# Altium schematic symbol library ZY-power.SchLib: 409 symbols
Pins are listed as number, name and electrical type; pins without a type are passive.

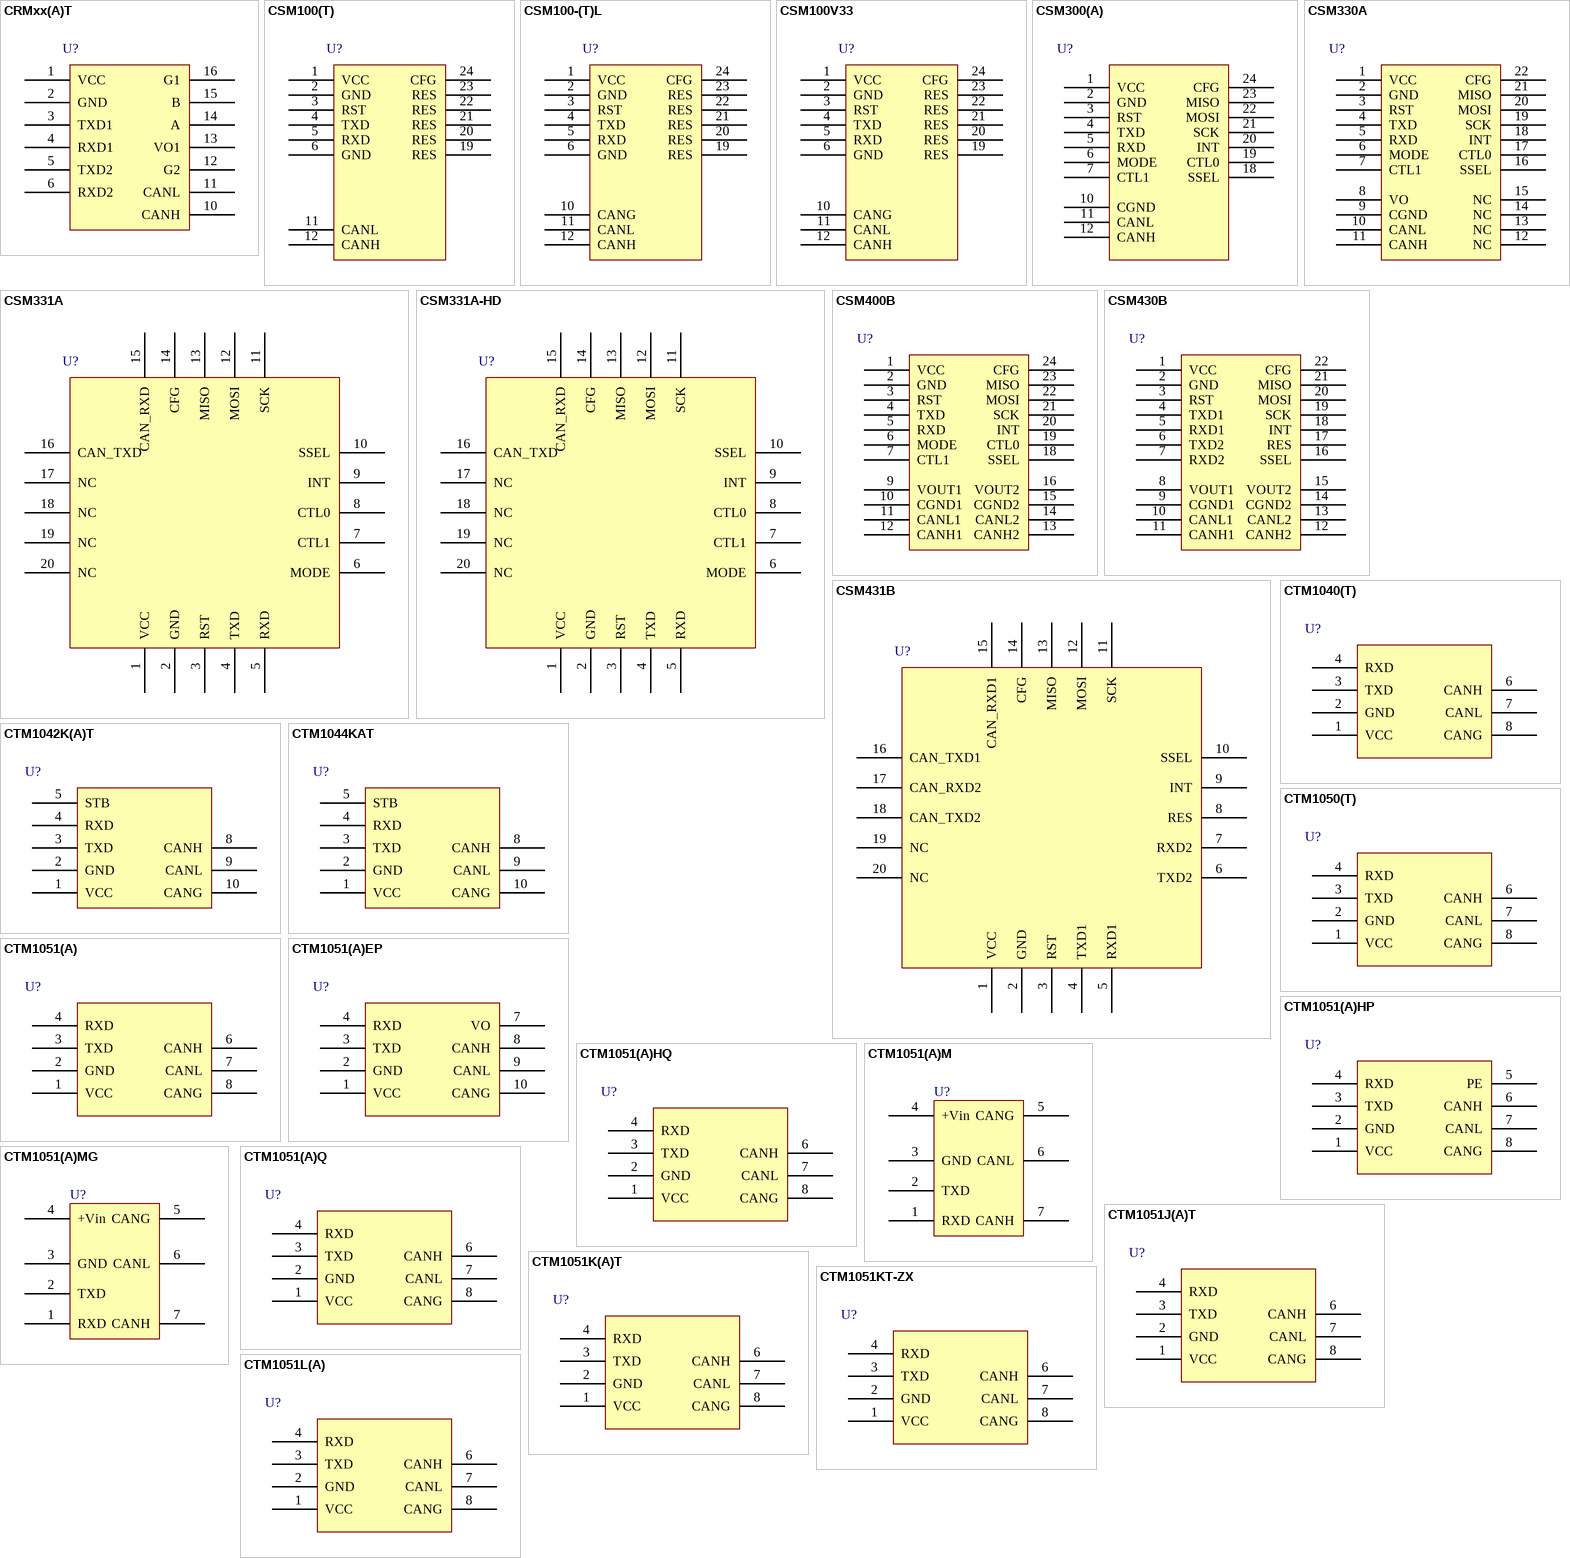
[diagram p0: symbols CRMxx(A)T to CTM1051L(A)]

## CRMxx(A)T
designator U?
footprint CRMxx(A)T
pins: 1 VCC, 2 GND, 3 TXD1, 4 RXD1, 5 TXD2, 6 RXD2, 10 CANH, 11 CANL, 12 G2, 13 VO1, 14 A, 15 B, 16 G1

## CSM100(T)
designator U?
footprint CSM100(T) (嵌入式CAN-bus接口芯片)
pins: 1 VCC, 2 GND, 3 RST, 4 TXD, 5 RXD, 6 GND, 11 CANL, 12 CANH, 19 RES, 20 RES, 21 RES, 22 RES, 23 RES, 24 CFG

## CSM100-(T)L
designator U?
footprint CSM100-(T)L
pins: 1 VCC, 2 GND, 3 RST, 4 TXD, 5 RXD, 6 GND, 10 CANG, 11 CANL, 12 CANH, 19 RES, 20 RES, 21 RES, 22 RES, 23 RES, 24 CFG

## CSM100V33
designator U?
footprint CSM100V33
pins: 1 VCC, 2 GND, 3 RST, 4 TXD, 5 RXD, 6 GND, 10 CANG, 11 CANL, 12 CANH, 19 RES, 20 RES, 21 RES, 22 RES, 23 RES, 24 CFG

## CSM300(A)
designator U?
footprint CSM300(A)
pins: 1 VCC, 2 GND, 3 RST, 4 TXD, 5 RXD, 6 MODE, 7 CTL1, 10 CGND, 11 CANL, 12 CANH, 18 SSEL, 19 CTL0, 20 INT, 21 SCK, 22 MOSI, 23 MISO, 24 CFG

## CSM330A
designator U?
CSM330A,ZLGLIB
footprint CSM330A
pins: 1 VCC, 2 GND, 3 RST, 4 TXD, 5 RXD, 6 MODE, 7 CTL1, 8 VO, 9 CGND, 10 CANL, 11 CANH, 12 NC, 13 NC, 14 NC, 15 NC, 16 SSEL, 17 CTL0, 18 INT, 19 SCK, 20 MOSI, 21 MISO, 22 CFG

## CSM331A
designator U?
footprint CSM331A
pins: 1 VCC, 2 GND, 3 RST, 4 TXD, 5 RXD, 6 MODE, 7 CTL1, 8 CTL0, 9 INT, 10 SSEL, 11 SCK, 12 MOSI, 13 MISO, 14 CFG, 15 CAN_RXD, 16 CAN_TXD, 17 NC, 18 NC, 19 NC, 20 NC

## CSM331A-HD
designator U?
footprint CSM331A-HD
pins: 1 VCC, 2 GND, 3 RST, 4 TXD, 5 RXD, 6 MODE, 7 CTL1, 8 CTL0, 9 INT, 10 SSEL, 11 SCK, 12 MOSI, 13 MISO, 14 CFG, 15 CAN_RXD, 16 CAN_TXD, 17 NC, 18 NC, 19 NC, 20 NC

## CSM400B
designator U?
footprint CSM400B (Footprint not found)
pins: 1 VCC, 2 GND, 3 RST, 4 TXD, 5 RXD, 6 MODE, 7 CTL1, 9 VOUT1, 10 CGND1, 11 CANL1, 12 CANH1, 13 CANH2, 14 CANL2, 15 CGND2, 16 VOUT2, 18 SSEL, 19 CTL0, 20 INT, 21 SCK, 22 MOSI, 23 MISO, 24 CFG

## CSM430B
designator U?
CSM430B,ZLGLIB
footprint CSM430B
pins: 1 VCC, 2 GND, 3 RST, 4 TXD1, 5 RXD1, 6 TXD2, 7 RXD2, 8 VOUT1, 9 CGND1, 10 CANL1, 11 CANH1, 12 CANH2, 13 CANL2, 14 CGND2, 15 VOUT2, 16 SSEL, 17 RES, 18 INT, 19 SCK, 20 MOSI, 21 MISO, 22 CFG

## CSM431B
designator U?
CSM431B,ZLGLIB
footprint CSM431B
pins: 1 VCC, 2 GND, 3 RST, 4 TXD1, 5 RXD1, 6 TXD2, 7 RXD2, 8 RES, 9 INT, 10 SSEL, 11 SCK, 12 MOSI, 13 MISO, 14 CFG, 15 CAN_RXD1, 16 CAN_TXD1, 17 CAN_RXD2, 18 CAN_TXD2, 19 NC, 20 NC

## CTM1040(T)
designator U?
footprint CTM1040(T)
pins: 1 VCC, 2 GND, 3 TXD, 4 RXD, 6 CANH, 7 CANL, 8 CANG

## CTM1042K(A)T
designator U?
footprint CTM1042K(A)T
pins: 1 VCC, 2 GND, 3 TXD, 4 RXD, 5 STB, 8 CANH, 9 CANL, 10 CANG

## CTM1044KAT
designator U?
footprint CTM1044KAT
pins: 1 VCC, 2 GND, 3 TXD, 4 RXD, 5 STB, 8 CANH, 9 CANL, 10 CANG

## CTM1050(T)
designator U?
footprint CTM1050(T)
pins: 1 VCC, 2 GND, 3 TXD, 4 RXD, 6 CANH, 7 CANL, 8 CANG

## CTM1051(A)
designator U?
footprint CTM1051(A)
pins: 1 VCC, 2 GND, 3 TXD, 4 RXD, 6 CANH, 7 CANL, 8 CANG

## CTM1051(A)EP
designator U?
footprint CTM1051(A)EP (Footprint not found)
pins: 1 VCC, 2 GND, 3 TXD, 4 RXD, 7 VO, 8 CANH, 9 CANL, 10 CANG

## CTM1051(A)HP
designator U?
footprint CTM1051(A)HP
pins: 1 VCC, 2 GND, 3 TXD, 4 RXD, 5 PE, 6 CANH, 7 CANL, 8 CANG

## CTM1051(A)HQ
designator U?
footprint CTM1051(A)HQ
pins: 1 VCC, 2 GND, 3 TXD, 4 RXD, 6 CANH, 7 CANL, 8 CANG

## CTM1051(A)M
designator U?
footprint CTM1051(A)M
pins: 1 RXD, 2 TXD, 3 GND, 4 +Vin, 5 CANG, 6 CANL, 7 CANH

## CTM1051(A)MG
designator U?
footprint CTM1051(A)MG
pins: 1 RXD, 2 TXD, 3 GND, 4 +Vin, 5 CANG, 6 CANL, 7 CANH

## CTM1051(A)Q
designator U?
footprint CTM1051(A)Q
pins: 1 VCC, 2 GND, 3 TXD, 4 RXD, 6 CANH, 7 CANL, 8 CANG

## CTM1051J(A)T
designator U?
footprint CTM1051J(A)T
pins: 1 VCC, 2 GND, 3 TXD, 4 RXD, 6 CANH, 7 CANL, 8 CANG

## CTM1051K(A)T
designator U?
footprint CTM1051K(A)T
pins: 1 VCC, 2 GND, 3 TXD, 4 RXD, 6 CANH, 7 CANL, 8 CANG

## CTM1051KT-ZX
designator U?
footprint CTM1051KT-ZX
pins: 1 VCC, 2 GND, 3 TXD, 4 RXD, 6 CANH, 7 CANL, 8 CANG

## CTM1051L(A)
designator U?
footprint CTM1051L(A)
pins: 1 VCC, 2 GND, 3 TXD, 4 RXD, 6 CANH, 7 CANL, 8 CANG

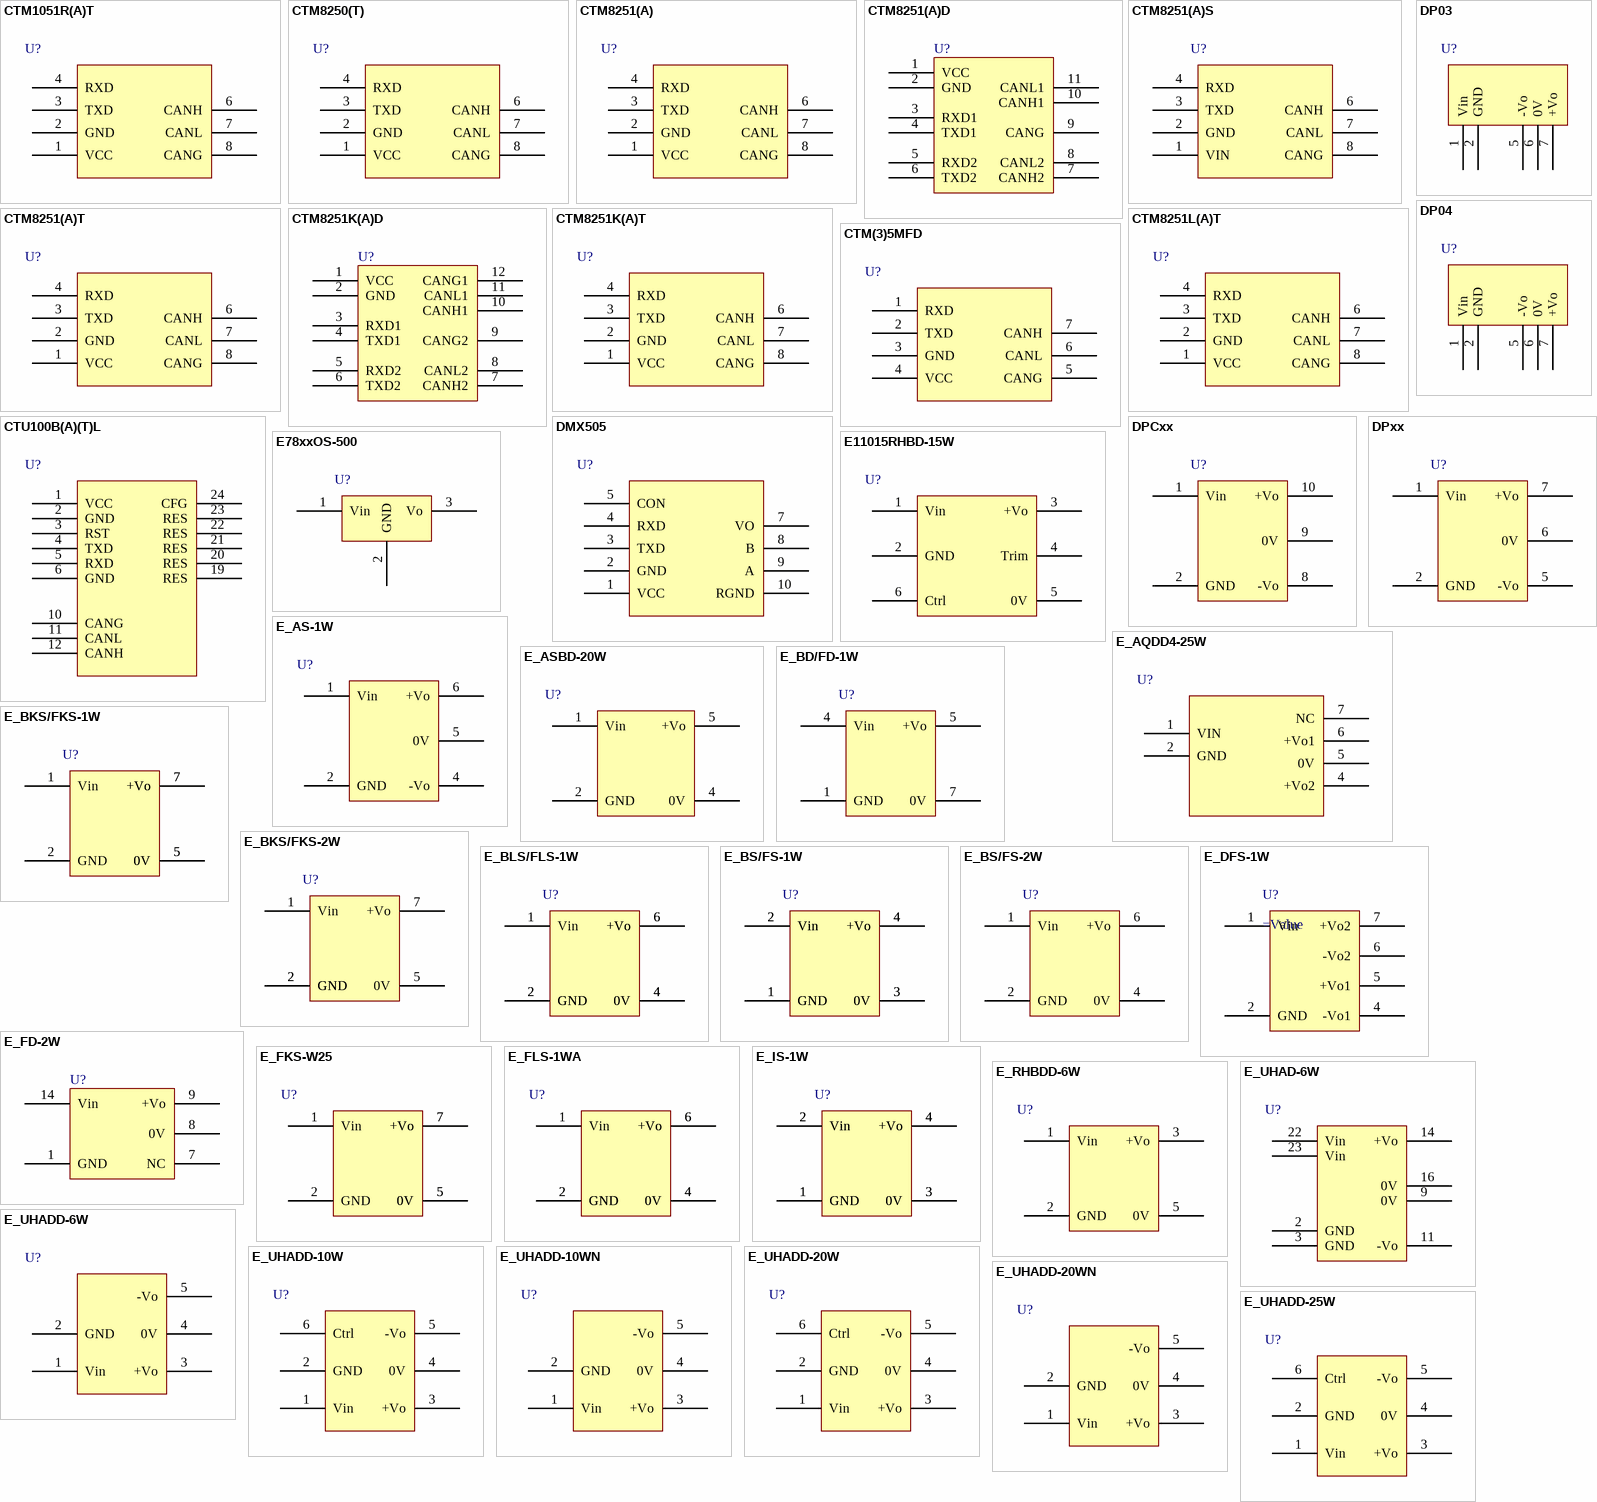
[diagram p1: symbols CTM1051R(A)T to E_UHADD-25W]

## CTM1051R(A)T
designator U?
footprint CTM1051R(A)T
pins: 1 VCC, 2 GND, 3 TXD, 4 RXD, 6 CANH, 7 CANL, 8 CANG

## CTM8250(T)
designator U?
footprint CTM8250(T)
pins: 1 VCC, 2 GND, 3 TXD, 4 RXD, 6 CANH, 7 CANL, 8 CANG

## CTM8251(A)
designator U?
footprint CTM8251(A)
pins: 1 VCC, 2 GND, 3 TXD, 4 RXD, 6 CANH, 7 CANL, 8 CANG

## CTM8251(A)D
designator U?
footprint CTM8251(A)D
pins: 1 VCC, 2 GND, 3 RXD1, 4 TXD1, 5 RXD2, 6 TXD2, 7 CANH2, 8 CANL2, 9 CANG, 10 CANH1, 11 CANL1

## CTM8251(A)S
designator U?
footprint CTM8251(A)S
pins: 1 VIN, 2 GND, 3 TXD, 4 RXD, 6 CANH, 7 CANL, 8 CANG

## CTM8251(A)T
designator U?
footprint CTM8251(A)T
pins: 1 VCC, 2 GND, 3 TXD, 4 RXD, 6 CANH, 7 CANL, 8 CANG

## CTM8251K(A)D
designator U?
footprint CTM8251K(A)D
pins: 1 VCC, 2 GND, 3 RXD1, 4 TXD1, 5 RXD2, 6 TXD2, 7 CANH2, 8 CANL2, 9 CANG2, 10 CANH1, 11 CANL1, 12 CANG1

## CTM8251K(A)T
designator U?
footprint CTM8251K(A)T
pins: 1 VCC, 2 GND, 3 TXD, 4 RXD, 6 CANH, 7 CANL, 8 CANG

## CTM8251L(A)T
designator U?
footprint CTM8251L(A)T
pins: 1 VCC, 2 GND, 3 TXD, 4 RXD, 6 CANH, 7 CANL, 8 CANG

## CTM(3)5MFD
designator U?
footprint CTM(3)5MFD
pins: 1 RXD, 2 TXD, 3 GND, 4 VCC, 5 CANG, 6 CANL, 7 CANH

## CTU100B(A)(T)L
designator U?
footprint CTU100B(A)(T)L
pins: 1 VCC, 2 GND, 3 RST, 4 TXD, 5 RXD, 6 GND, 10 CANG, 11 CANL, 12 CANH, 19 RES, 20 RES, 21 RES, 22 RES, 23 RES, 24 CFG

## DMX505
designator U?
footprint DMX505
pins: 1 VCC, 2 GND, 3 TXD, 4 RXD, 5 CON, 7 VO, 8 B, 9 A, 10 RGND

## DP03
designator U?
footprint DP03
pins: 1 Vin, 2 GND, 5 -Vo, 6 0V, 7 +Vo

## DP04
designator U?
footprint DP04
pins: 1 Vin, 2 GND, 5 -Vo, 6 0V, 7 +Vo

## DPCxx
designator U?
footprint DPCxx
pins: 1 Vin, 2 GND, 8 -Vo, 9 0V, 10 +Vo

## DPxx
designator U?
footprint DPxx
pins: 1 Vin, 2 GND, 5 -Vo, 6 0V, 7 +Vo

## E78xxOS-500
designator U?
footprint E78xxOS-500
pins: 1 Vin, 2 GND, 3 Vo

## E11015RHBD-15W
designator U?
footprint E11015RHBD-15W
pins: 1 Vin, 2 GND, 3 +Vo, 4 Trim, 5 0V, 6 Ctrl

## E_AQDD4-25W
designator U?
footprint E_AQDD4-25W
pins: 1 VIN, 2 GND, 4 +Vo2, 5 0V, 6 +Vo1, 7 NC

## E_AS-1W
designator U?
footprint E_AS-1W
pins: 1 Vin, 2 GND, 4 -Vo, 5 0V, 6 +Vo

## E_ASBD-20W
designator U?
footprint E_ASBD-20W
pins: 1 Vin, 2 GND, 4 0V, 5 +Vo

## E_BD/FD-1W
designator U?
footprint E_BD/FD-1W
pins: 1 GND, 4 Vin, 5 +Vo, 7 0V

## E_BKS/FKS-1W
designator U?
footprint E_BKS/FKS-1W
pins: 1 Vin, 2 GND, 5 0V, 5 0V, 7 +Vo, 7 +Vo

## E_BKS/FKS-2W
designator U?
footprint E_BKS/FKS-2W
pins: 1 Vin, 2 GND, 2 GND, 5 0V, 7 +Vo

## E_BLS/FLS-1W
designator U?
footprint E_BLS/FLS-1W
pins: 1 Vin, 2 GND, 2 GND, 4 0V, 4 0V, 6 +Vo, 6 +Vo

## E_BS/FS-1W
designator U?
footprint E_BS/FS-1W
pins: 1 GND, 1 GND, 2 Vin, 2 Vin, 3 0V, 3 0V, 4 +Vo, 4 +Vo

## E_BS/FS-2W
designator U?
footprint E_BS/FS-2W
pins: 1 Vin, 2 GND, 4 0V, 6 +Vo

## E_DFS-1W
designator U?
footprint E_DFS-1W
pins: 1 Vin, 2 GND, 4 -Vo1, 5 +Vo1, 6 -Vo2, 7 +Vo2

## E_FD-2W
designator U?
footprint E_FD-2W
pins: 1 GND, 7 NC, 8 0V, 9 +Vo, 14 Vin

## E_FKS-W25
designator U?
footprint E_FKS-W25
pins: 1 Vin, 2 GND, 5 0V, 5 0V, 7 +Vo, 7 +Vo

## E_FLS-1WA
designator U?
footprint E_FLS-1WA
pins: 1 Vin, 2 GND, 2 GND, 4 0V, 4 0V, 6 +Vo, 6 +Vo

## E_IS-1W
designator U?
footprint E_IS-1W
pins: 1 GND, 1 GND, 2 Vin, 2 Vin, 3 0V, 3 0V, 4 +Vo, 4 +Vo

## E_RHBDD-6W
designator U?
footprint E_RHBDD-6W
pins: 1 Vin, 2 GND, 3 +Vo, 5 0V

## E_UHAD-6W
designator U?
footprint E_UHAD-6W
pins: 2 GND, 3 GND, 9 0V, 11 -Vo, 14 +Vo, 16 0V, 22 Vin, 23 Vin

## E_UHADD-6W
designator U?
footprint E_UHADD-6W
pins: 1 Vin, 2 GND, 3 +Vo, 4 0V, 5 -Vo

## E_UHADD-10W
designator U?
footprint E_UHADD-10W
pins: 1 Vin, 2 GND, 3 +Vo, 4 0V, 5 -Vo, 6 Ctrl

## E_UHADD-10WN
designator U?
footprint E_UHADD-10WN
pins: 1 Vin, 2 GND, 3 +Vo, 4 0V, 5 -Vo

## E_UHADD-20W
designator U?
footprint E_UHADD-20W
pins: 1 Vin, 2 GND, 3 +Vo, 4 0V, 5 -Vo, 6 Ctrl

## E_UHADD-20WN
designator U?
footprint E_UHADD-20WN
pins: 1 Vin, 2 GND, 3 +Vo, 4 0V, 5 -Vo

## E_UHADD-25W
designator U?
footprint E_UHADD-25W
pins: 1 Vin, 2 GND, 3 +Vo, 4 0V, 5 -Vo, 6 Ctrl

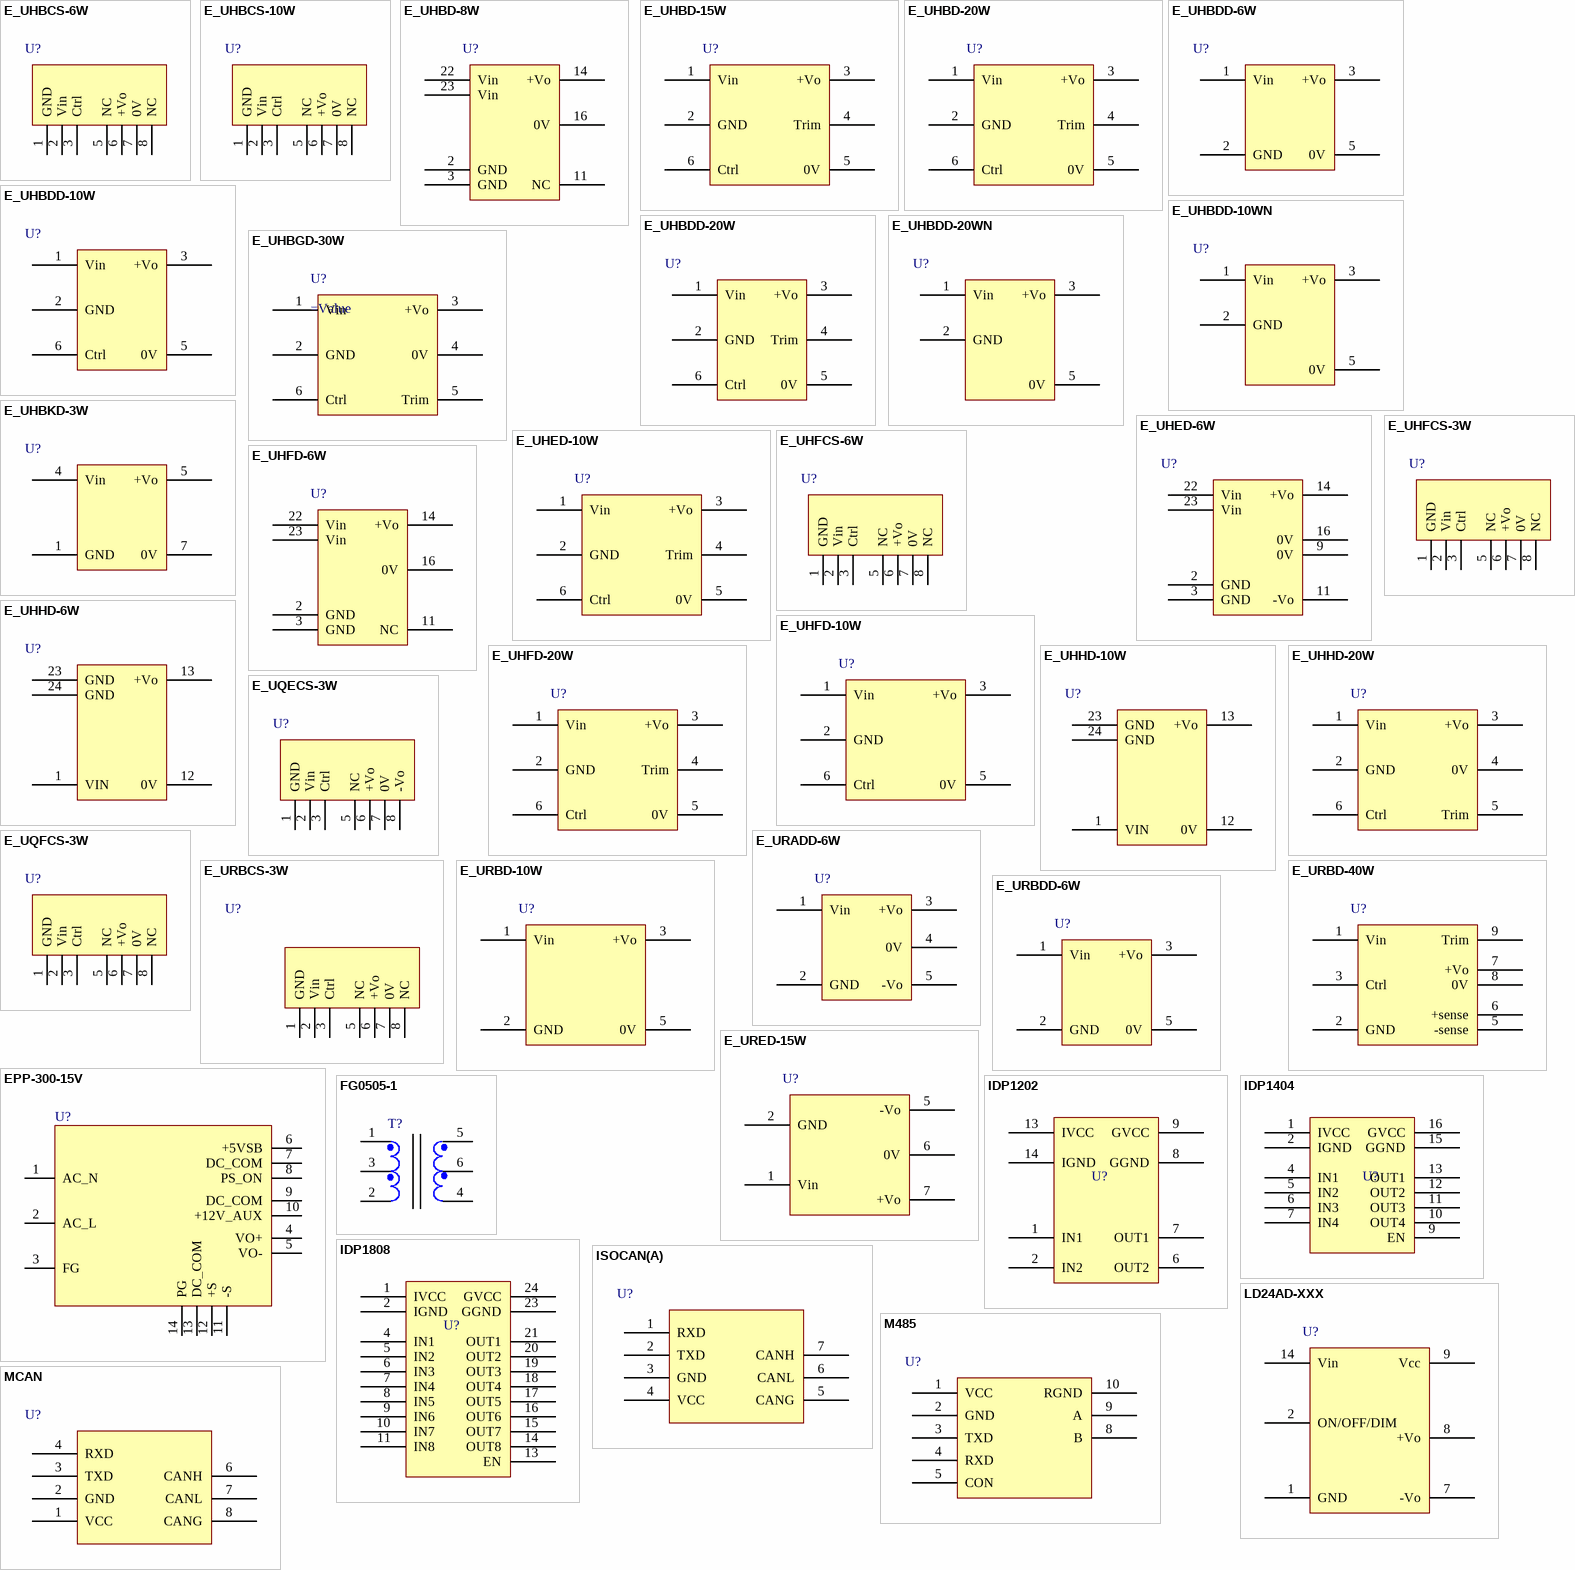
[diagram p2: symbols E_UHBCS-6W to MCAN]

## E_UHBCS-6W
designator U?
footprint E_UHBCS-6W
pins: 1 GND, 2 Vin, 3 Ctrl, 5 NC, 6 +Vo, 7 0V, 8 NC

## E_UHBCS-10W
designator U?
footprint E_UHBCS-10W
pins: 1 GND, 2 Vin, 3 Ctrl, 5 NC, 6 +Vo, 7 0V, 8 NC

## E_UHBD-8W
designator U?
footprint E_UHBD-8W
pins: 2 GND, 3 GND, 11 NC, 14 +Vo, 16 0V, 22 Vin, 23 Vin

## E_UHBD-15W
designator U?
footprint E_UHBD-15W
pins: 1 Vin, 2 GND, 3 +Vo, 4 Trim, 5 0V, 6 Ctrl

## E_UHBD-20W
designator U?
footprint E_UHBD-20W
pins: 1 Vin, 2 GND, 3 +Vo, 4 Trim, 5 0V, 6 Ctrl

## E_UHBDD-6W
designator U?
footprint E_UHBDD-6W
pins: 1 Vin, 2 GND, 3 +Vo, 5 0V

## E_UHBDD-10W
designator U?
footprint E_UHBDD-10W
pins: 1 Vin, 2 GND, 3 +Vo, 5 0V, 6 Ctrl

## E_UHBDD-10WN
designator U?
footprint E_UHBDD-10WN
pins: 1 Vin, 2 GND, 3 +Vo, 5 0V

## E_UHBDD-20W
designator U?
footprint E_UHBDD-20W
pins: 1 Vin, 2 GND, 3 +Vo, 4 Trim, 5 0V, 6 Ctrl

## E_UHBDD-20WN
designator U?
footprint E_UHBDD-20WN
pins: 1 Vin, 2 GND, 3 +Vo, 5 0V

## E_UHBGD-30W
designator U?
footprint E_UHBGD-30W
pins: 1 Vin, 2 GND, 3 +Vo, 4 0V, 5 Trim, 6 Ctrl

## E_UHBKD-3W
designator U?
footprint E_UHBKD-3W
pins: 1 GND, 4 Vin, 5 +Vo, 7 0V

## E_UHED-6W
designator U?
footprint E_UHED-6W
pins: 2 GND, 3 GND, 9 0V, 11 -Vo, 14 +Vo, 16 0V, 22 Vin, 23 Vin

## E_UHED-10W
designator U?
footprint E_UHED-10W
pins: 1 Vin, 2 GND, 3 +Vo, 4 Trim, 5 0V, 6 Ctrl

## E_UHFCS-3W
designator U?
footprint E_UHFCS-3W
pins: 1 GND, 2 Vin, 3 Ctrl, 5 NC, 6 +Vo, 7 0V, 8 NC

## E_UHFCS-6W
designator U?
footprint E_UHFCS-6W
pins: 1 GND, 2 Vin, 3 Ctrl, 5 NC, 6 +Vo, 7 0V, 8 NC

## E_UHFD-6W
designator U?
footprint E_UHFD-6W
pins: 2 GND, 3 GND, 11 NC, 14 +Vo, 16 0V, 22 Vin, 23 Vin

## E_UHFD-10W
designator U?
footprint E_UHFD-10W
pins: 1 Vin, 2 GND, 3 +Vo, 5 0V, 6 Ctrl

## E_UHFD-20W
designator U?
footprint E_UHFD-20W
pins: 1 Vin, 2 GND, 3 +Vo, 4 Trim, 5 0V, 6 Ctrl

## E_UHHD-6W
designator U?
footprint E_UHHD-6W
pins: 1 VIN, 12 0V, 13 +Vo, 23 GND, 24 GND

## E_UHHD-10W
designator U?
footprint E_UHHD-10W
pins: 1 VIN, 12 0V, 13 +Vo, 23 GND, 24 GND

## E_UHHD-20W
designator U?
footprint E_UHHD-20W
pins: 1 Vin, 2 GND, 3 +Vo, 4 0V, 5 Trim, 6 Ctrl

## E_UQECS-3W
designator U?
footprint E_UQECS-3W
pins: 1 GND, 2 Vin, 3 Ctrl, 5 NC, 6 +Vo, 7 0V, 8 -Vo

## E_UQFCS-3W
designator U?
footprint E_UQFCS-3W
pins: 1 GND, 2 Vin, 3 Ctrl, 5 NC, 6 +Vo, 7 0V, 8 NC

## E_URADD-6W
designator U?
footprint E_URADD-6W
pins: 1 Vin, 2 GND, 3 +Vo, 4 0V, 5 -Vo

## E_URBCS-3W
designator U?
footprint E_URBCS-3W
pins: 1 GND, 2 Vin, 3 Ctrl, 5 NC, 6 +Vo, 7 0V, 8 NC

## E_URBD-10W
designator U?
footprint E_URBD-10W
pins: 1 Vin, 2 GND, 3 +Vo, 5 0V

## E_URBD-40W
designator U?
footprint E_URBD-40W
pins: 1 Vin, 2 GND, 3 Ctrl, 5 -sense, 6 +sense, 7 +Vo, 8 0V, 9 Trim

## E_URBDD-6W
designator U?
footprint E_URBDD-6W
pins: 1 Vin, 2 GND, 3 +Vo, 5 0V

## E_URED-15W
designator U?
footprint E_URED-15W
pins: 1 Vin, 2 GND, 5 -Vo, 6 0V, 7 +Vo

## EPP-300-15V
designator U?
footprint epp-300-15V
pins: 1 AC_N, 2 AC_L, 3 FG, 4 VO+, 5 VO-, 6 +5VSB, 7 DC_COM, 8 PS_ON, 9 DC_COM, 10 +12V_AUX, 11 -S, 12 +S, 13 DC_COM, 14 PG

## FG0505-1
designator T?
TRANS6D
footprint FG0505-1
pins: 1, 2, 3, 4, 5, 6

## IDP1202
designator U?
footprint IDP1202 (20x10x8mm)
pins: 1 IN1, 2 IN2, 6 OUT2, 7 OUT1, 8 GGND, 9 GVCC, 13 IVCC, 14 IGND

## IDP1404
designator U?
footprint IDP1404 (23.97x14.41x9.65mm)
pins: 1 IVCC, 2 IGND, 4 IN1, 5 IN2, 6 IN3, 7 IN4, 9 EN, 10 OUT4, 11 OUT3, 12 OUT2, 13 OUT1, 15 GGND, 16 GVCC

## IDP1808
designator U?
footprint IDP1808 (32.32x14.41x6.7(9.65)mm)
pins: 1 IVCC, 2 IGND, 4 IN1, 5 IN2, 6 IN3, 7 IN4, 8 IN5, 9 IN6, 10 IN7, 11 IN8, 13 EN, 14 OUT8, 15 OUT7, 16 OUT6, 17 OUT5, 18 OUT4, 19 OUT3, 20 OUT2, 21 OUT1, 23 GGND, 24 GVCC

## ISOCAN(A)
designator U?
footprint ISOCAN(A)
pins: 1 RXD, 2 TXD, 3 GND, 4 VCC, 5 CANG, 6 CANL, 7 CANH

## LD24AD-XXX
designator U?
footprint LD24AD-XXX
pins: 1 GND, 2 ON/OFF/DIM, 7 -Vo, 8 +Vo, 9 Vcc, 14 Vin

## M485
designator U?
footprint M485
pins: 1 VCC, 2 GND, 3 TXD, 4 RXD, 5 CON, 8 B, 9 A, 10 RGND

## MCAN
designator U?
footprint MCAN
pins: 1 VCC, 2 GND, 3 TXD, 4 RXD, 6 CANH, 7 CANL, 8 CANG

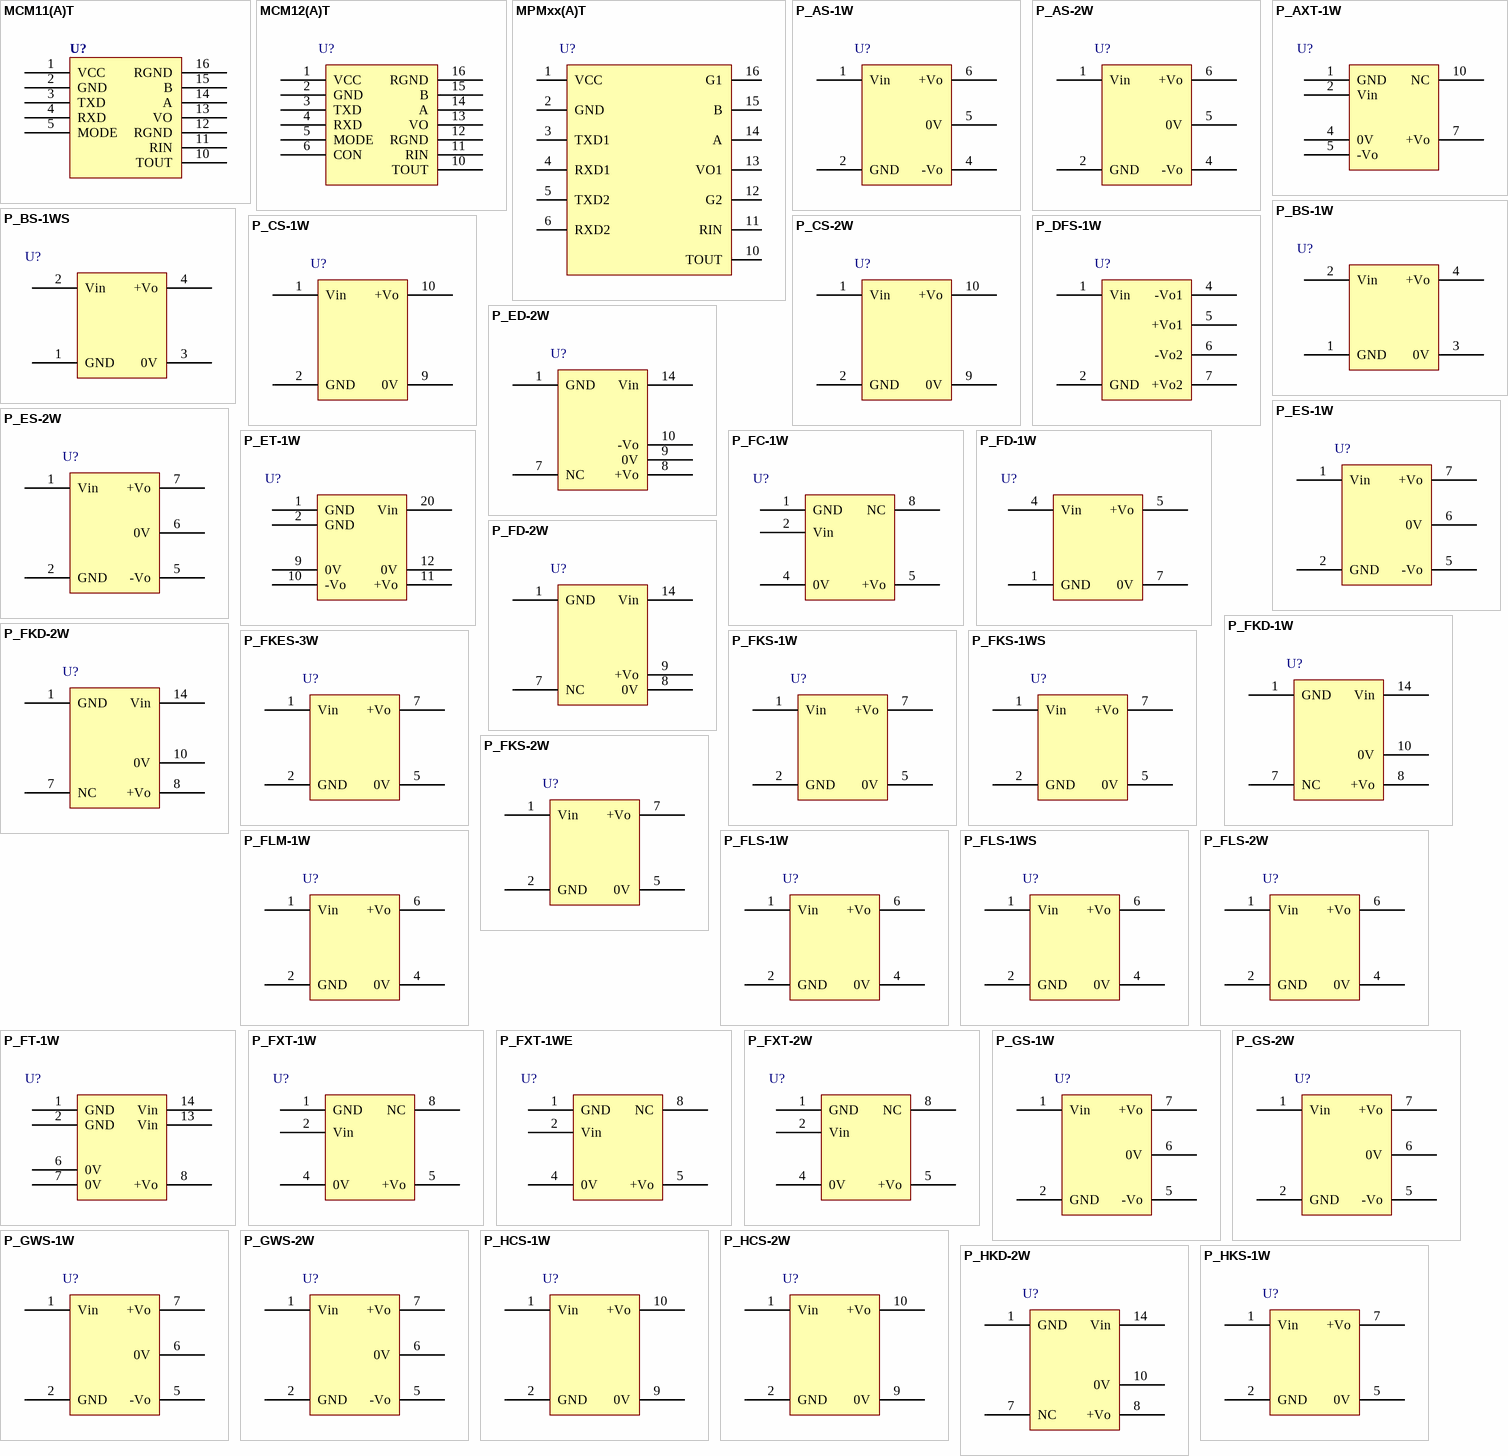
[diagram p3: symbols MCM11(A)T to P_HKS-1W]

## MCM11(A)T
designator U?
footprint MCM11(A)T
pins: 1 VCC, 2 GND, 3 TXD, 4 RXD, 5 MODE, 10 TOUT, 11 RIN, 12 RGND, 13 VO, 14 A, 15 B, 16 RGND

## MCM12(A)T
designator U?
footprint MCM12(A)T
pins: 1 VCC, 2 GND, 3 TXD, 4 RXD, 5 MODE, 6 CON, 10 TOUT, 11 RIN, 12 RGND, 13 VO, 14 A, 15 B, 16 RGND

## MPMxx(A)T
designator U?
footprint MPMxx(A)T
pins: 1 VCC, 2 GND, 3 TXD1, 4 RXD1, 5 TXD2, 6 RXD2, 10 TOUT, 11 RIN, 12 G2, 13 VO1, 14 A, 15 B, 16 G1

## P_AS-1W
designator U?
footprint P_AS-1W
pins: 1 Vin, 2 GND, 4 -Vo, 5 0V, 6 +Vo

## P_AS-2W
designator U?
footprint P_AS-2W
pins: 1 Vin, 2 GND, 4 -Vo, 5 0V, 6 +Vo

## P_AXT-1W
designator U?
footprint P_AXT-1W
pins: 1 GND, 2 Vin, 4 0V, 5 -Vo, 7 +Vo, 10 NC

## P_BS-1W
designator U?
footprint P_BS-1W
pins: 1 GND, 2 Vin, 3 0V, 4 +Vo

## P_BS-1WS
designator U?
footprint P_BS-1WS
pins: 1 GND, 2 Vin, 3 0V, 4 +Vo

## P_CS-1W
designator U?
footprint P_CS-1W
pins: 1 Vin, 2 GND, 9 0V, 10 +Vo

## P_CS-2W
designator U?
footprint P_CS-2W
pins: 1 Vin, 2 GND, 9 0V, 10 +Vo

## P_DFS-1W
designator U?
footprint P_DFS-1W
pins: 1 Vin, 2 GND, 4 -Vo1, 5 +Vo1, 6 -Vo2, 7 +Vo2

## P_ED-2W
designator U?
footprint P_ED-2W
pins: 1 GND, 7 NC, 8 +Vo, 9 0V, 10 -Vo, 14 Vin

## P_ES-1W
designator U?
footprint P_ES-1W
pins: 1 Vin, 2 GND, 5 -Vo, 6 0V, 7 +Vo

## P_ES-2W
designator U?
footprint P_ES-2W (Footprint not found)
pins: 1 Vin, 2 GND, 5 -Vo, 6 0V, 7 +Vo

## P_ET-1W
designator U?
footprint P_ET-1W
pins: 1 GND, 2 GND, 9 0V, 10 -Vo, 11 +Vo, 12 0V, 20 Vin

## P_FC-1W
designator U?
footprint P_FC-1W
pins: 1 GND, 2 Vin, 4 0V, 5 +Vo, 8 NC

## P_FD-1W
designator U?
footprint P_FD-1W
pins: 1 GND, 4 Vin, 5 +Vo, 7 0V

## P_FD-2W
designator U?
footprint P_FD-2W
pins: 1 GND, 7 NC, 8 0V, 9 +Vo, 14 Vin

## P_FKD-1W
designator U?
footprint P_FKD-1W
pins: 1 GND, 7 NC, 8 +Vo, 10 0V, 14 Vin

## P_FKD-2W
designator U?
footprint P_FKD-2W (Footprint not found)
pins: 1 GND, 7 NC, 8 +Vo, 10 0V, 14 Vin

## P_FKES-3W
designator U?
footprint P_FKES-3W
pins: 1 Vin, 2 GND, 5 0V, 7 +Vo

## P_FKS-1W
designator U?
footprint P_FKS-1W
pins: 1 Vin, 2 GND, 5 0V, 7 +Vo

## P_FKS-1WS
designator U?
footprint P_FKS-1WS (Footprint not found)
pins: 1 Vin, 2 GND, 5 0V, 7 +Vo

## P_FKS-2W
designator U?
footprint P_FKS-2W
pins: 1 Vin, 2 GND, 5 0V, 7 +Vo

## P_FLM-1W
designator U?
footprint P_FLM-1W
pins: 1 Vin, 2 GND, 4 0V, 6 +Vo

## P_FLS-1W
designator U?
footprint P_FLS-1W
pins: 1 Vin, 2 GND, 4 0V, 6 +Vo

## P_FLS-1WS
designator U?
footprint P_FLS-1WS
pins: 1 Vin, 2 GND, 4 0V, 6 +Vo

## P_FLS-2W
designator U?
footprint P_FLS-2W
pins: 1 Vin, 2 GND, 4 0V, 6 +Vo

## P_FT-1W
designator U?
footprint P_FT-1W
pins: 1 GND, 2 GND, 6 0V, 7 0V, 8 +Vo, 13 Vin, 14 Vin

## P_FXT-1W
designator U?
footprint P_FXT-1W
pins: 1 GND, 2 Vin, 4 0V, 5 +Vo, 8 NC

## P_FXT-1WE
designator U?
footprint P_FXT-1WE
pins: 1 GND, 2 Vin, 4 0V, 5 +Vo, 8 NC

## P_FXT-2W
designator U?
footprint P_FXT-2W
pins: 1 GND, 2 Vin, 4 0V, 5 +Vo, 8 NC

## P_GS-1W
designator U?
footprint P_GS-1W
pins: 1 Vin, 2 GND, 5 -Vo, 6 0V, 7 +Vo

## P_GS-2W
designator U?
footprint P_GS-2W
pins: 1 Vin, 2 GND, 5 -Vo, 6 0V, 7 +Vo

## P_GWS-1W
designator U?
footprint P_GWS-1W
pins: 1 Vin, 2 GND, 5 -Vo, 6 0V, 7 +Vo

## P_GWS-2W
designator U?
footprint P_GWS-2W
pins: 1 Vin, 2 GND, 5 -Vo, 6 0V, 7 +Vo

## P_HCS-1W
designator U?
footprint P_HCS-1W
pins: 1 Vin, 2 GND, 9 0V, 10 +Vo

## P_HCS-2W
designator U?
footprint P_HCS-2W
pins: 1 Vin, 2 GND, 9 0V, 10 +Vo

## P_HKD-2W
designator U?
footprint P_HKD-2W
pins: 1 GND, 7 NC, 8 +Vo, 10 0V, 14 Vin

## P_HKS-1W
designator U?
footprint P_HKS-1W
pins: 1 Vin, 2 GND, 5 0V, 7 +Vo

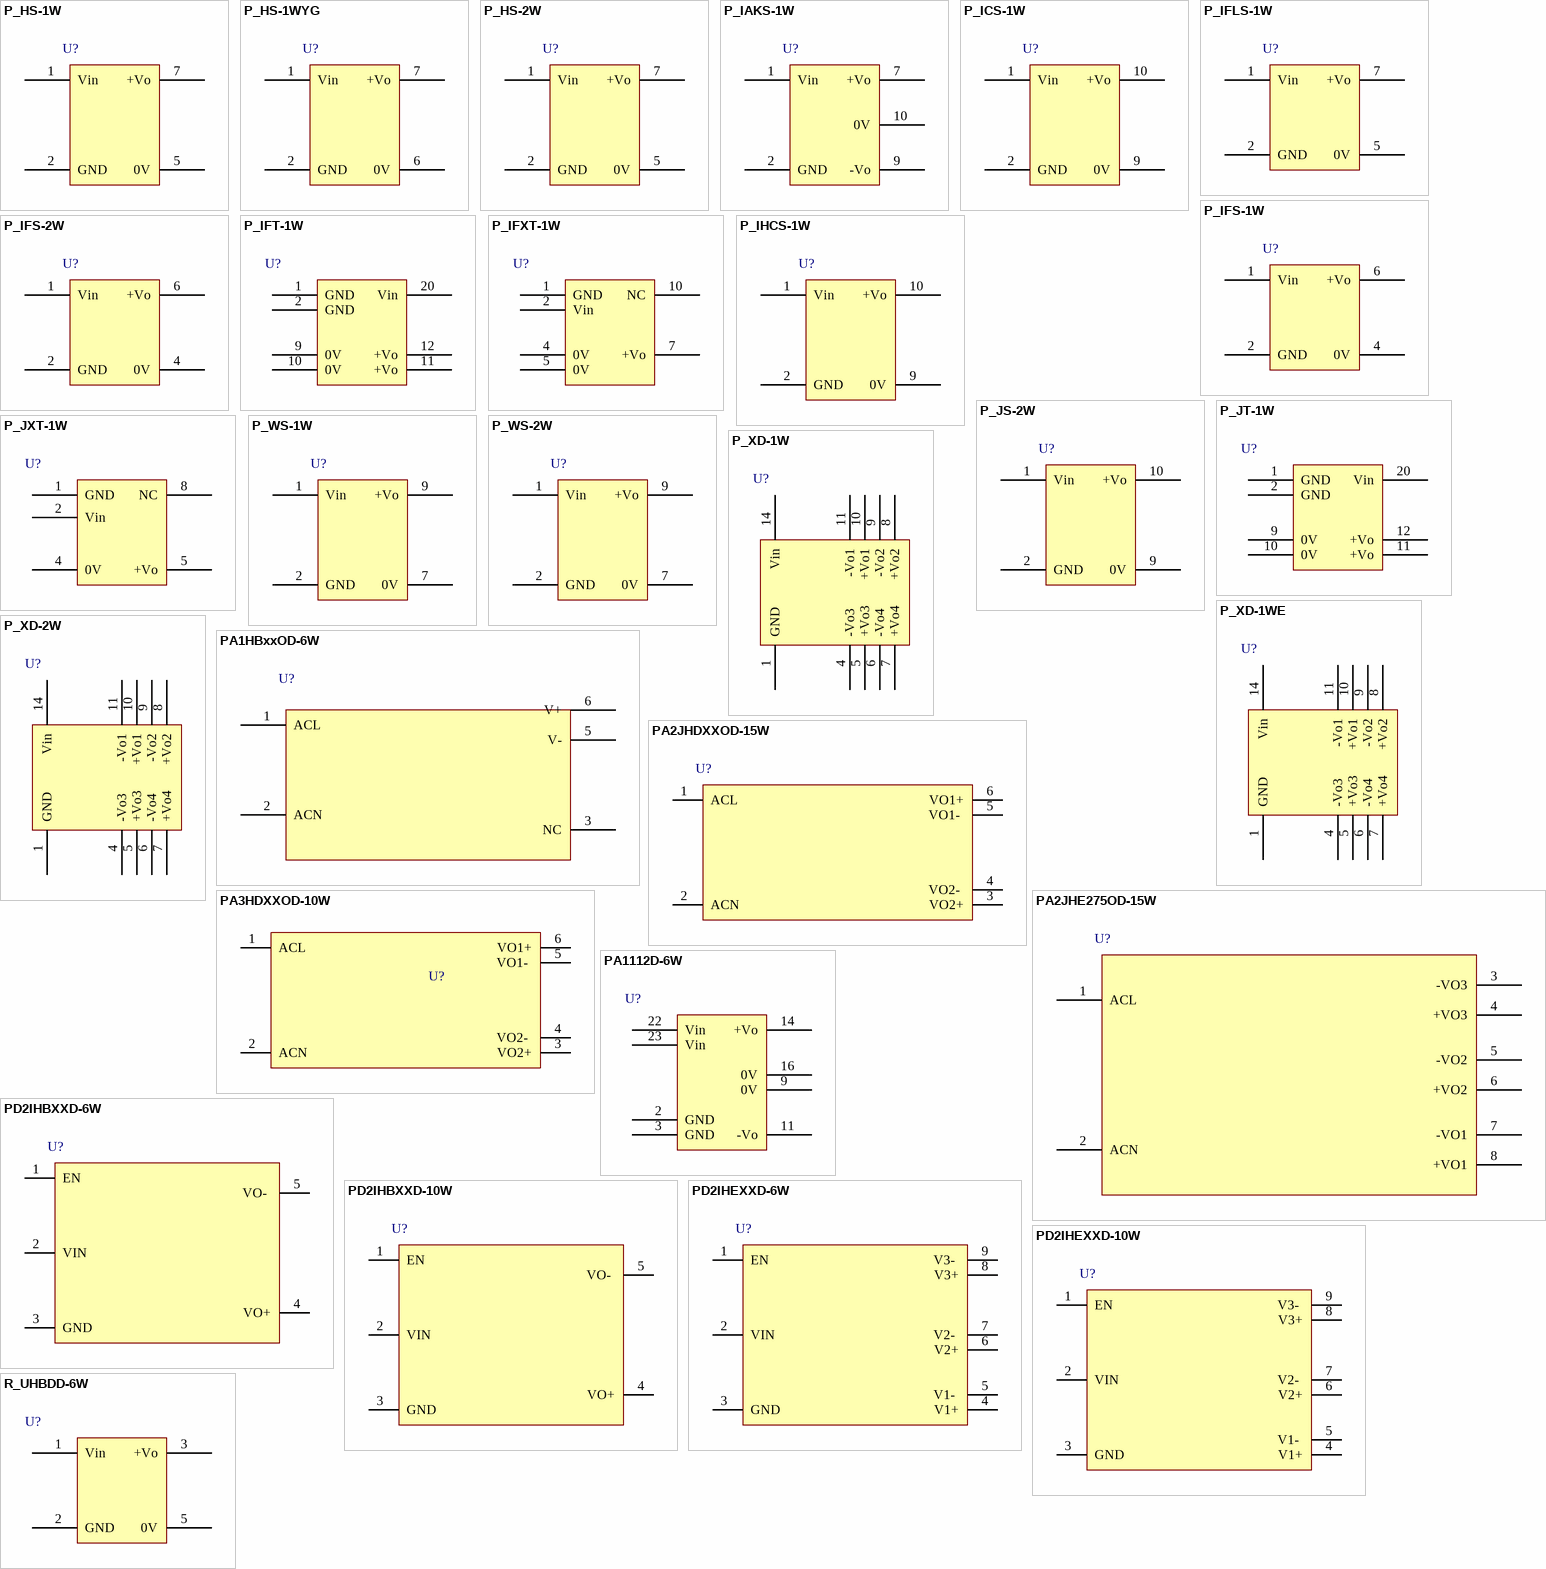
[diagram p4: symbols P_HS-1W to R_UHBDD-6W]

## P_HS-1W
designator U?
footprint P_HS-1W
pins: 1 Vin, 2 GND, 5 0V, 7 +Vo

## P_HS-1WYG
designator U?
footprint P_HS-1WYG
pins: 1 Vin, 2 GND, 6 0V, 7 +Vo

## P_HS-2W
designator U?
footprint P_HS-2W (Footprint not found)
pins: 1 Vin, 2 GND, 5 0V, 7 +Vo

## P_IAKS-1W
designator U?
footprint P_IAKS-1W
pins: 1 Vin, 2 GND, 7 +Vo, 9 -Vo, 10 0V

## P_ICS-1W
designator U?
footprint P_ICS-1W (Footprint not found)
pins: 1 Vin, 2 GND, 9 0V, 10 +Vo

## P_IFLS-1W
designator U?
footprint P_IFLS-1W
pins: 1 Vin, 2 GND, 5 0V, 7 +Vo

## P_IFS-1W
designator U?
footprint P_IFS-1W (Footprint not found)
pins: 1 Vin, 2 GND, 4 0V, 6 +Vo

## P_IFS-2W
designator U?
footprint P_IFS-2W
pins: 1 Vin, 2 GND, 4 0V, 6 +Vo

## P_IFT-1W
designator U?
footprint P_IFT-1W
pins: 1 GND, 2 GND, 9 0V, 10 0V, 11 +Vo, 12 +Vo, 20 Vin

## P_IFXT-1W
designator U?
footprint P_IFXT-1W (Footprint not found)
pins: 1 GND, 2 Vin, 4 0V, 5 0V, 7 +Vo, 10 NC

## P_IHCS-1W
designator U?
footprint P_IHCS-1W
pins: 1 Vin, 2 GND, 9 0V, 10 +Vo

## P_JS-2W
designator U?
footprint P_JS-2W
pins: 1 Vin, 2 GND, 9 0V, 10 +Vo

## P_JT-1W
designator U?
footprint P_JT-1W
pins: 1 GND, 2 GND, 9 0V, 10 0V, 11 +Vo, 12 +Vo, 20 Vin

## P_JXT-1W
designator U?
footprint P_JXT-1W
pins: 1 GND, 2 Vin, 4 0V, 5 +Vo, 8 NC

## P_WS-1W
designator U?
footprint P_WS-1W (Footprint not found)
pins: 1 Vin, 2 GND, 7 0V, 9 +Vo

## P_WS-2W
designator U?
footprint P_WS-2W
pins: 1 Vin, 2 GND, 7 0V, 9 +Vo

## P_XD-1W
designator U?
footprint P_XD-1W (Footprint not found)
pins: 1 GND, 4 -Vo3, 5 +Vo3, 6 -Vo4, 7 +Vo4, 8 +Vo2, 9 -Vo2, 10 +Vo1, 11 -Vo1, 14 Vin

## P_XD-1WE
designator U?
footprint P_XD-1WE
pins: 1 GND, 4 -Vo3, 5 +Vo3, 6 -Vo4, 7 +Vo4, 8 +Vo2, 9 -Vo2, 10 +Vo1, 11 -Vo1, 14 Vin

## P_XD-2W
designator U?
footprint P_XD-2W
pins: 1 GND, 4 -Vo3, 5 +Vo3, 6 -Vo4, 7 +Vo4, 8 +Vo2, 9 -Vo2, 10 +Vo1, 11 -Vo1, 14 Vin

## PA1HBxxOD-6W
designator U?
footprint PA1HBxxOD-6W
pins: 1 ACL, 2 ACN, 3 NC, 5 V-, 6 V+

## PA2JHDXXOD-15W
designator U?
footprint PA2JHDXXOD-15W
pins: 1 ACL, 2 ACN, 3 VO2+, 4 VO2- , 5 VO1- , 6 VO1+

## PA2JHE275OD-15W
designator U?
footprint PA2JHE275OD-15W
pins: 1 ACL, 2 ACN, 3 -VO3, 4 +VO3, 5 -VO2, 6 +VO2, 7 -VO1, 8 +VO1

## PA3HDXXOD-10W
designator U?
footprint PA3HDXXOD-10W
pins: 1 ACL, 2 ACN, 3 VO2+, 4 VO2- , 5 VO1- , 6 VO1+

## PA1112D-6W
designator U?
footprint PA1112D-6W
pins: 2 GND, 3 GND, 9 0V, 11 -Vo, 14 +Vo, 16 0V, 22 Vin, 23 Vin

## PD2IHBXXD-6W
designator U?
footprint PD2IHBXXD-6W
pins: 1 EN, 2 VIN, 3 GND, 4 VO+, 5 VO- 

## PD2IHBXXD-10W
designator U?
footprint PD2IHBXXD-10W
pins: 1 EN, 2 VIN, 3 GND, 4 VO+, 5 VO- 

## PD2IHEXXD-6W
designator U?
footprint PD2IHEXXD-6W
pins: 1 EN, 2 VIN, 3 GND, 4 V1+, 5 V1- , 6 V2+, 7 V2- , 8 V3+, 9 V3- 

## PD2IHEXXD-10W
designator U?
footprint PD2IHEXXD-10W
pins: 1 EN, 2 VIN, 3 GND, 4 V1+, 5 V1- , 6 V2+, 7 V2- , 8 V3+, 9 V3- 

## R_UHBDD-6W
designator U?
footprint R_UHBDD-6W
pins: 1 Vin, 2 GND, 3 +Vo, 5 0V

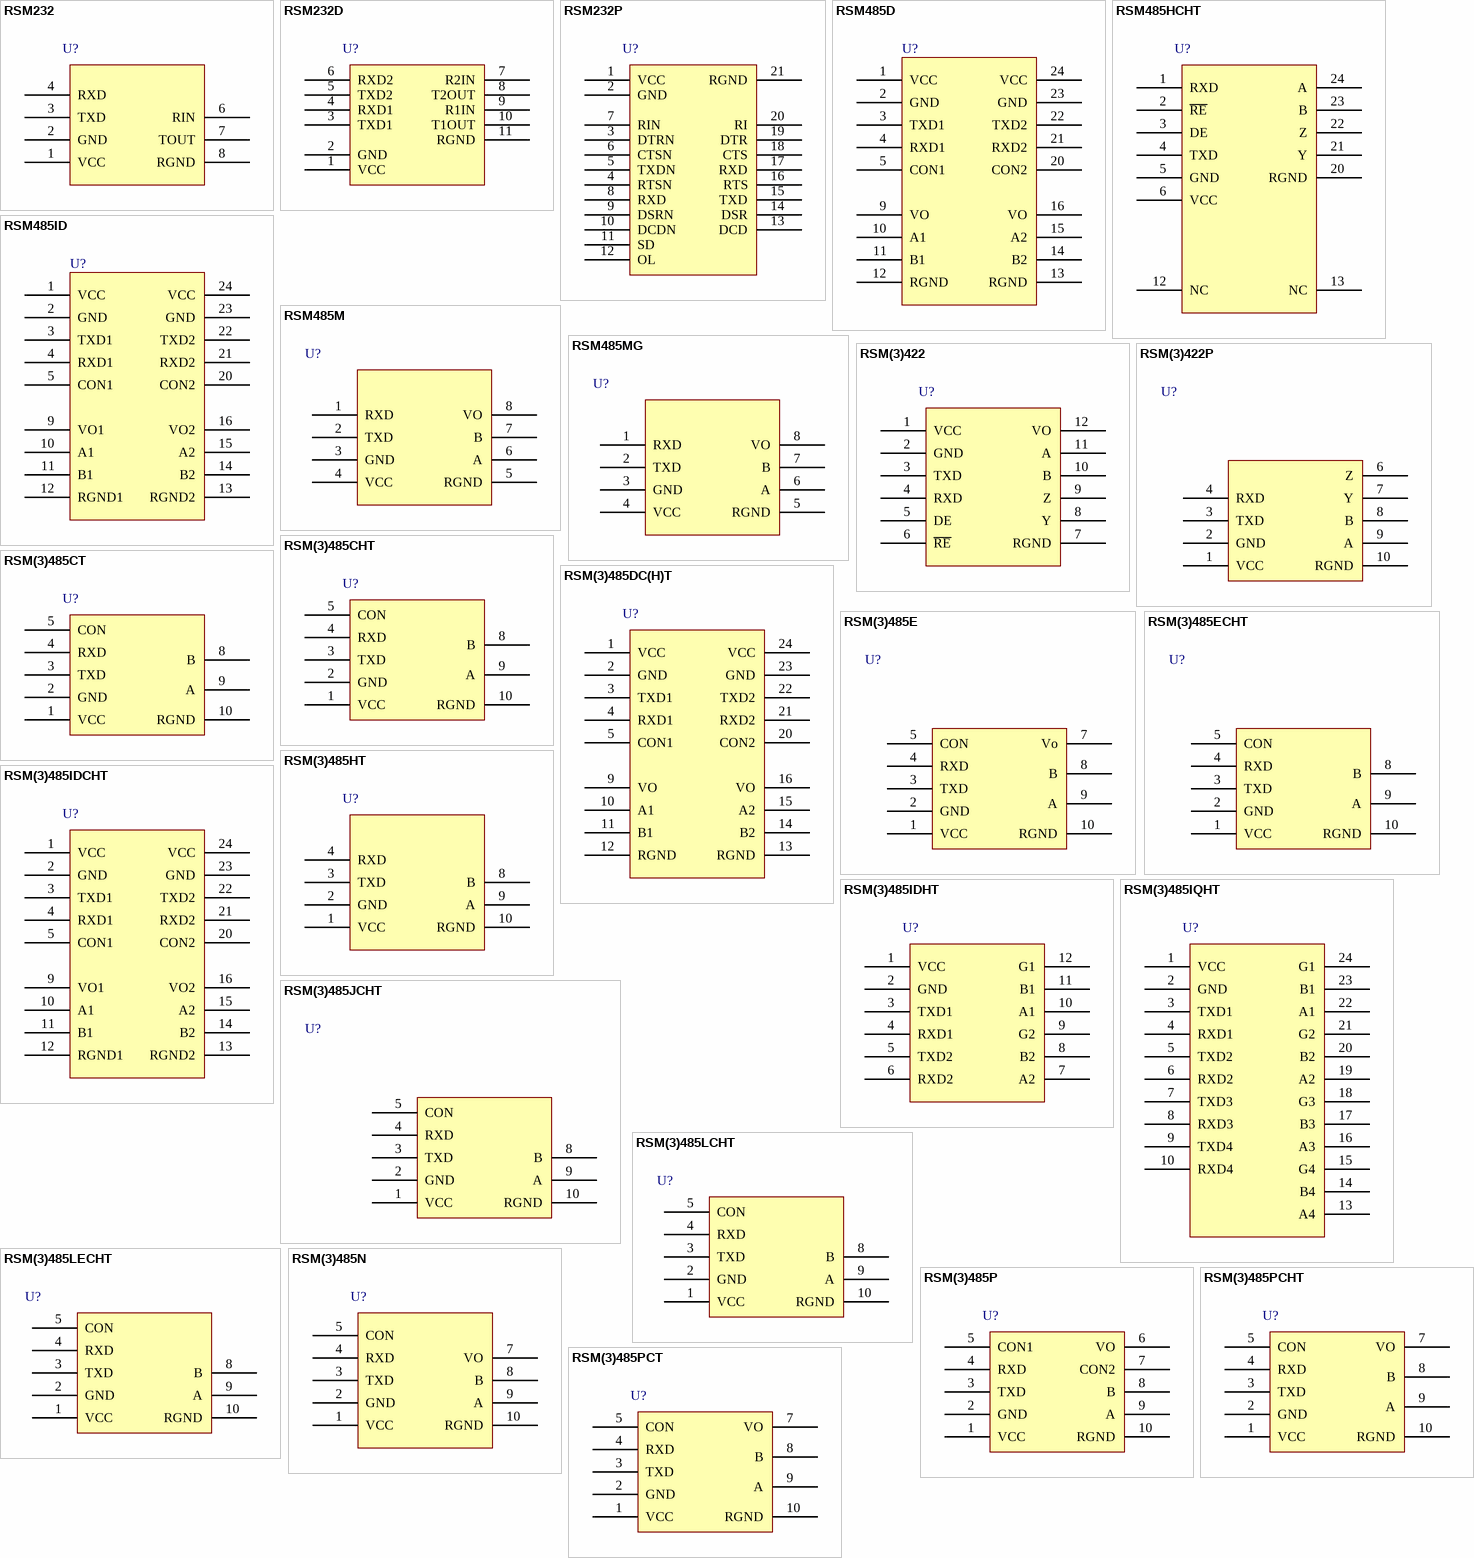
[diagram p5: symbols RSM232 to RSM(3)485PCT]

## RSM232
designator U?
footprint RSM232
pins: 1 VCC, 2 GND, 3 TXD, 4 RXD, 6 RIN, 7 TOUT, 8 RGND

## RSM232D
designator U?
footprint RSM232D
pins: 1 VCC, 2 GND, 3 TXD1, 4 RXD1, 5 TXD2, 6 RXD2, 7 R2IN, 8 T2OUT, 9 R1IN, 10 T1OUT, 11 RGND

## RSM232P
designator U?
footprint RSM232P
pins: 1 VCC, 2 GND, 3 DTRN, 4 RTSN, 5 TXDN, 6 CTSN, 7 RIN, 8 RXD, 9 DSRN, 10 DCDN, 11 SD, 12 OL, 13 DCD, 14 DSR, 15 TXD, 16 RTS, 17 RXD, 18 CTS, 19 DTR, 20 RI, 21 RGND

## RSM485D
designator U?
footprint RSM485D
pins: 1 VCC, 2 GND, 3 TXD1, 4 RXD1, 5 CON1, 9 VO, 10 A1, 11 B1, 12 RGND, 13 RGND, 14 B2, 15 A2, 16 VO, 20 CON2, 21 RXD2, 22 TXD2, 23 GND, 24 VCC
2 alternate drawings of the same symbol

## RSM485HCHT
designator U?
footprint RSM485HCHT
pins: 1 RXD, 2 ~{RE}, 3 DE, 4 TXD, 5 GND, 6 VCC, 12 NC, 13 NC, 20 RGND, 21 Y, 22 Z, 23 B, 24 A

## RSM485ID
designator U?
footprint RSM485ID
pins: 1 VCC, 2 GND, 3 TXD1, 4 RXD1, 5 CON1, 9 VO1, 10 A1, 11 B1, 12 RGND1, 13 RGND2, 14 B2, 15 A2, 16 VO2, 20 CON2, 21 RXD2, 22 TXD2, 23 GND, 24 VCC
2 alternate drawings of the same symbol

## RSM485M
designator U?
footprint RSM485M
pins: 1 RXD, 2 TXD, 3 GND, 4 VCC, 5 RGND, 6 A, 7 B, 8 VO

## RSM485MG
designator U?
footprint RSM485MG
pins: 1 RXD, 2 TXD, 3 GND, 4 VCC, 5 RGND, 6 A, 7 B, 8 VO

## RSM(3)422
designator U?
footprint RSM(3)422
pins: 1 VCC, 2 GND, 3 TXD, 4 RXD, 5 DE, 6 ~{RE}, 7 RGND, 8 Y, 9 Z, 10 B, 11 A, 12 VO

## RSM(3)422P
designator U?
footprint RSM(3)422P
pins: 1 VCC, 2 GND, 3 TXD, 4 RXD, 6 Z, 7 Y, 8 B, 9 A, 10 RGND
2 alternate drawings of the same symbol

## RSM(3)485CHT
designator U?
footprint RSM(3)485CHT (嵌入式隔离RS-485收发器)
pins: 1 VCC, 2 GND, 3 TXD, 4 RXD, 5 CON, 8 B, 9 A, 10 RGND

## RSM(3)485CT
designator U?
footprint RSM(3)485CT (嵌入式隔离RS-485收发器)
pins: 1 VCC, 2 GND, 3 TXD, 4 RXD, 5 CON, 8 B, 9 A, 10 RGND

## RSM(3)485DC(H)T
designator U?
footprint RSM(3)485DC(H)T
pins: 1 VCC, 2 GND, 3 TXD1, 4 RXD1, 5 CON1, 9 VO, 10 A1, 11 B1, 12 RGND, 13 RGND, 14 B2, 15 A2, 16 VO, 20 CON2, 21 RXD2, 22 TXD2, 23 GND, 24 VCC

## RSM(3)485E
designator U?
footprint RSM(3)485E
pins: 1 VCC, 2 GND, 3 TXD, 4 RXD, 5 CON, 7 Vo, 8 B, 9 A, 10 RGND
2 alternate drawings of the same symbol

## RSM(3)485ECHT
designator U?
footprint RSM(3)485ECHT
pins: 1 VCC, 2 GND, 3 TXD, 4 RXD, 5 CON, 8 B, 9 A, 10 RGND
2 alternate drawings of the same symbol

## RSM(3)485HT
designator U?
footprint RSM(3)485HT
pins: 1 VCC, 2 GND, 3 TXD, 4 RXD, 8 B, 9 A, 10 RGND

## RSM(3)485IDCHT
designator U?
footprint RSM(3)485IDCHT
pins: 1 VCC, 2 GND, 3 TXD1, 4 RXD1, 5 CON1, 9 VO1, 10 A1, 11 B1, 12 RGND1, 13 RGND2, 14 B2, 15 A2, 16 VO2, 20 CON2, 21 RXD2, 22 TXD2, 23 GND, 24 VCC

## RSM(3)485IDHT
designator U?
footprint RSM(3)485IDHT
pins: 1 VCC, 2 GND, 3 TXD1, 4 RXD1, 5 TXD2, 6 RXD2, 7 A2, 8 B2, 9 G2, 10 A1, 11 B1, 12 G1

## RSM(3)485IQHT
designator U?
footprint RSM(3)485IQHT
pins: 1 VCC, 2 GND, 3 TXD1, 4 RXD1, 5 TXD2, 6 RXD2, 7 TXD3, 8 RXD3, 9 TXD4, 10 RXD4, 13 A4, 14 B4, 15 G4, 16 A3, 17 B3, 18 G3, 19 A2, 20 B2, 21 G2, 22 A1, 23 B1, 24 G1

## RSM(3)485JCHT
designator U?
footprint RSM(3)485JCHT
pins: 1 VCC, 2 GND, 3 TXD, 4 RXD, 5 CON, 8 B, 9 A, 10 RGND
2 alternate drawings of the same symbol

## RSM(3)485LCHT
designator U?
footprint RSM(3)485LCHT
pins: 1 VCC, 2 GND, 3 TXD, 4 RXD, 5 CON, 8 B, 9 A, 10 RGND

## RSM(3)485LECHT
designator U?
footprint RSM(3)485LECHT
pins: 1 VCC, 2 GND, 3 TXD, 4 RXD, 5 CON, 8 B, 9 A, 10 RGND

## RSM(3)485N
designator U?
footprint RSM(3)485N
pins: 1 VCC, 2 GND, 3 TXD, 4 RXD, 5 CON, 7 VO, 8 B, 9 A, 10 RGND

## RSM(3)485P
designator U?
footprint RSM(3)485P
pins: 1 VCC, 2 GND, 3 TXD, 4 RXD, 5 CON1, 6 VO, 7 CON2, 8 B, 9 A, 10 RGND

## RSM(3)485PCHT
designator U?
footprint RSM(3)485PCHT
pins: 1 VCC, 2 GND, 3 TXD, 4 RXD, 5 CON, 7 VO, 8 B, 9 A, 10 RGND

## RSM(3)485PCT
designator U?
footprint RSM(3)485PCT
pins: 1 VCC, 2 GND, 3 TXD, 4 RXD, 5 CON, 7 VO, 8 B, 9 A, 10 RGND

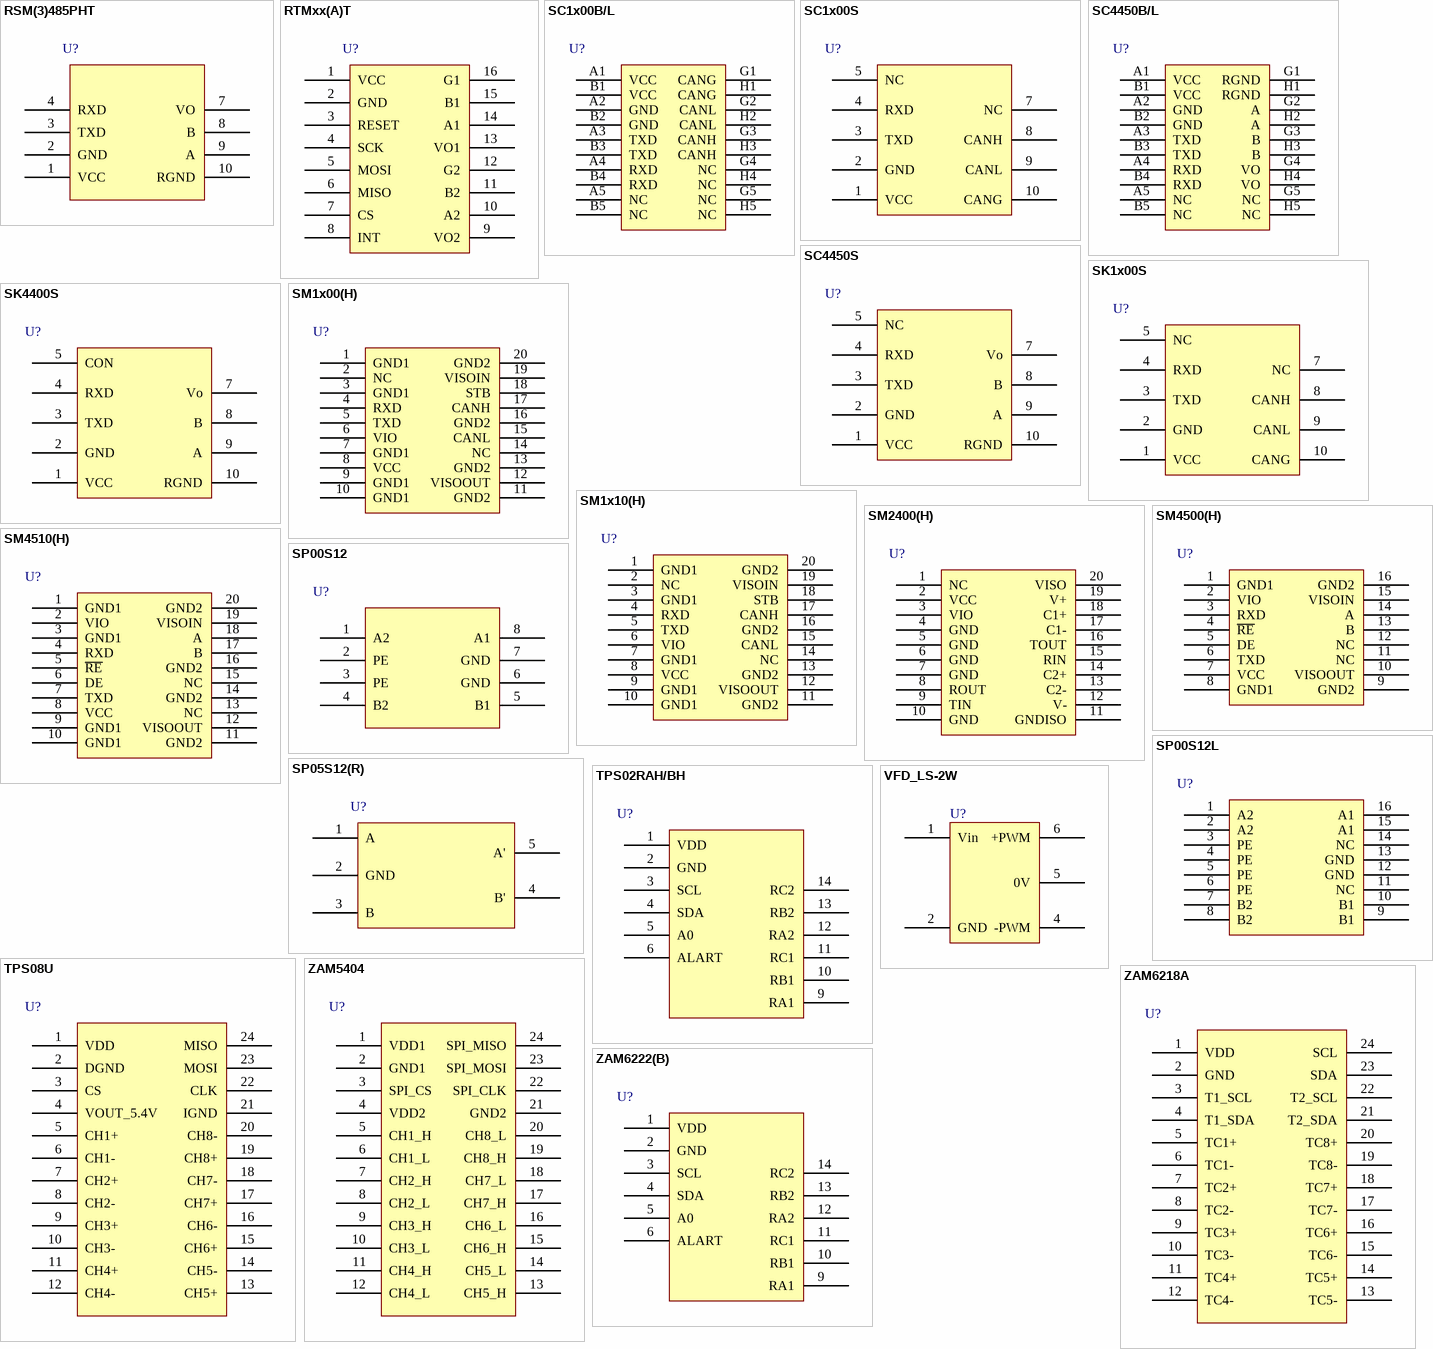
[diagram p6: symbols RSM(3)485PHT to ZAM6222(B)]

## RSM(3)485PHT
designator U?
footprint RSM(3)485PHT
pins: 1 VCC, 2 GND, 3 TXD, 4 RXD, 7 VO, 8 B, 9 A, 10 RGND

## RTMxx(A)T
designator U?
footprint RTMxx(A)T
pins: 1 VCC, 2 GND, 3 RESET, 4 SCK, 5 MOSI, 6 MISO, 7 CS, 8 INT, 9 VO2, 10 A2, 11 B2, 12 G2, 13 VO1, 14 A1, 15 B1, 16 G1

## SC1x00B/L
designator U?
footprint SC1x00B/L
pins: A1 VCC, A2 GND, A3 TXD, A4 RXD, A5 NC, B1 VCC, B2 GND, B3 TXD, B4 RXD, B5 NC, G1 CANG, G2 CANL, G3 CANH, G4 NC, G5 NC, H1 CANG, H2 CANL, H3 CANH, H4 NC, H5 NC

## SC1x00S
designator U?
footprint SC1x00S
pins: 1 VCC, 2 GND, 3 TXD, 4 RXD, 5 NC, 7 NC, 8 CANH, 9 CANL, 10 CANG

## SC4450B/L
designator U?
footprint SC4450B/L
pins: A1 VCC, A2 GND, A3 TXD, A4 RXD, A5 NC, B1 VCC, B2 GND, B3 TXD, B4 RXD, B5 NC, G1 RGND, G2 A, G3 B, G4 VO, G5 NC, H1 RGND, H2 A, H3 B, H4 VO, H5 NC

## SC4450S
designator U?
footprint SC4450S
pins: 1 VCC, 2 GND, 3 TXD, 4 RXD, 5 NC, 7 Vo, 8 B, 9 A, 10 RGND

## SK1x00S
designator U?
footprint SK1x00S
pins: 1 VCC, 2 GND, 3 TXD, 4 RXD, 5 NC, 7 NC, 8 CANH, 9 CANL, 10 CANG

## SK4400S
designator U?
footprint SK4400S
pins: 1 VCC, 2 GND, 3 TXD, 4 RXD, 5 CON, 7 Vo, 8 B, 9 A, 10 RGND

## SM1x00(H)
designator U?
footprint SM1x00(H)
pins: 1 GND1, 2 NC, 3 GND1, 4 RXD, 5 TXD, 6 VIO, 7 GND1, 8 VCC, 9 GND1, 10 GND1, 11 GND2, 12 VISOOUT, 13 GND2, 14 NC, 15 CANL, 16 GND2, 17 CANH, 18 STB, 19 VISOIN, 20 GND2

## SM1x10(H)
designator U?
footprint SM1x10(H)
pins: 1 GND1, 2 NC, 3 GND1, 4 RXD, 5 TXD, 6 VIO, 7 GND1, 8 VCC, 9 GND1, 10 GND1, 11 GND2, 12 VISOOUT, 13 GND2, 14 NC, 15 CANL, 16 GND2, 17 CANH, 18 STB, 19 VISOIN, 20 GND2

## SM2400(H)
designator U?
footprint SM2400(H)
pins: 1 NC, 2 VCC, 3 VIO, 4 GND, 5 GND, 6 GND, 7 GND, 8 ROUT, 9 TIN, 10 GND, 11 GNDISO, 12 V-, 13 C2-, 14 C2+, 15 RIN, 16 TOUT, 17 C1-, 18 C1+, 19 V+, 20 VISO

## SM4500(H)
designator U?
footprint SM4500(H)
pins: 1 GND1, 2 VIO, 3 RXD, 4 ~{RE}, 5 DE, 6 TXD, 7 VCC, 8 GND1, 9 GND2, 10 VISOOUT, 11 NC, 12 NC, 13 B, 14 A, 15 VISOIN, 16 GND2

## SM4510(H)
designator U?
footprint SM4510(H)
pins: 1 GND1, 2 VIO, 3 GND1, 4 RXD, 5 ~{RE}, 6 DE, 7 TXD, 8 VCC, 9 GND1, 10 GND1, 11 GND2, 12 VISOOUT, 13 NC, 14 GND2, 15 NC, 16 GND2, 17 B, 18 A, 19 VISOIN, 20 GND2

## SP00S12
designator U?
footprint SP00S12
pins: 1 A2, 2 PE, 3 PE, 4 B2, 5 B1, 6 GND, 7 GND, 8 A1

## SP00S12L
designator U?
footprint SP00S12L
pins: 1 A2, 2 A2, 3 PE, 4 PE, 5 PE, 6 PE, 7 B2, 8 B2, 9 B1, 10 B1, 11 NC, 12 GND, 13 GND, 14 NC, 15 A1, 16 A1

## SP05S12(R)
designator U?
footprint SP05S12(R)
pins: 1 A, 2 GND, 3 B, 4 B', 5 A'

## TPS02RAH/BH
designator U?
footprint TPS02RAH/BH
pins: 1 VDD, 2 GND, 3 SCL, 4 SDA, 5 A0, 6 ALART, 9 RA1, 10 RB1, 11 RC1, 12 RA2, 13 RB2, 14 RC2

## TPS08U
designator U?
footprint TPS08U
pins: 1 VDD, 2 DGND, 3 CS, 4 VOUT_5.4V, 5 CH1+, 6 CH1-, 7 CH2+, 8 CH2-, 9 CH3+, 10 CH3-, 11 CH4+, 12 CH4-, 13 CH5+, 14 CH5-, 15 CH6+, 16 CH6-, 17 CH7+, 18 CH7-, 19 CH8+, 20 CH8-, 21 IGND, 22 CLK, 23 MOSI, 24 MISO

## VFD_LS-2W
designator U?
footprint VFD_LS-2W
pins: 1 Vin, 2 GND, 4 -PWM, 5 0V, 6 +PWM

## ZAM5404
designator U?
footprint ZAM5404
pins: 1 VDD1, 2 GND1, 3 SPI_CS, 4 VDD2, 5 CH1_H, 6 CH1_L, 7 CH2_H, 8 CH2_L, 9 CH3_H, 10 CH3_L, 11 CH4_H, 12 CH4_L, 13 CH5_H, 14 CH5_L, 15 CH6_H, 16 CH6_L, 17 CH7_H, 18 CH7_L, 19 CH8_H, 20 CH8_L, 21 GND2, 22 SPI_CLK, 23 SPI_MOSI, 24 SPI_MISO

## ZAM6218A
designator U?
footprint ZAM6218A
pins: 1 VDD, 2 GND, 3 T1_SCL, 4 T1_SDA, 5 TC1+, 6 TC1-, 7 TC2+, 8 TC2-, 9 TC3+, 10 TC3-, 11 TC4+, 12 TC4-, 13 TC5-, 14 TC5+, 15 TC6-, 16 TC6+, 17 TC7-, 18 TC7+, 19 TC8-, 20 TC8+, 21 T2_SDA, 22 T2_SCL, 23 SDA, 24 SCL

## ZAM6222(B)
designator U?
footprint ZAM6222(B)
pins: 1 VDD, 2 GND, 3 SCL, 4 SDA, 5 A0, 6 ALART, 9 RA1, 10 RB1, 11 RC1, 12 RA2, 13 RB2, 14 RC2

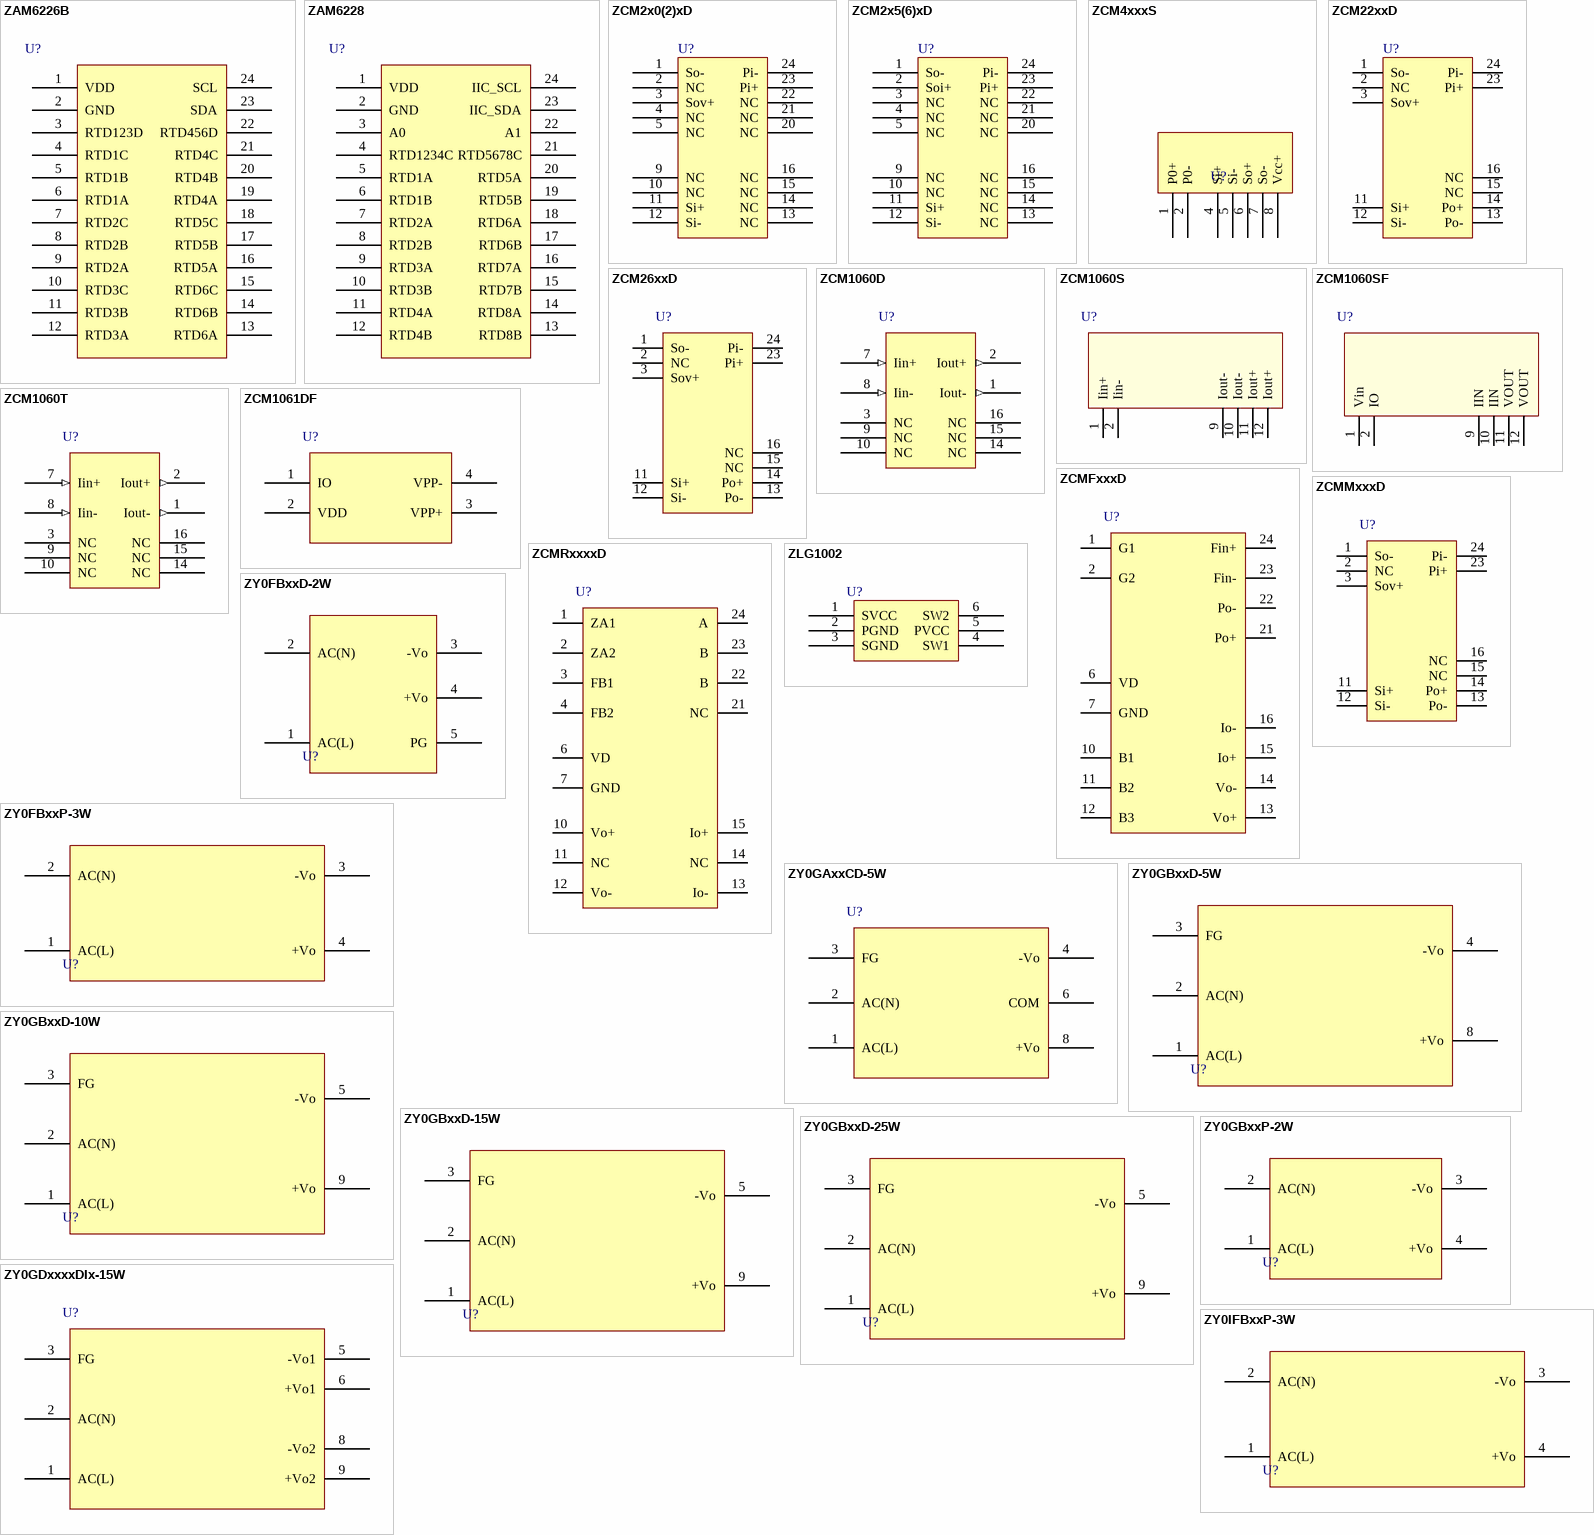
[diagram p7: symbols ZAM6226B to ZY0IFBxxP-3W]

## ZAM6226B
designator U?
footprint ZAM6226B
pins: 1 VDD, 2 GND, 3 RTD123D, 4 RTD1C, 5 RTD1B, 6 RTD1A, 7 RTD2C, 8 RTD2B, 9 RTD2A, 10 RTD3C, 11 RTD3B, 12 RTD3A, 13 RTD6A, 14 RTD6B, 15 RTD6C, 16 RTD5A, 17 RTD5B, 18 RTD5C, 19 RTD4A, 20 RTD4B, 21 RTD4C, 22 RTD456D, 23 SDA, 24 SCL

## ZAM6228
designator U?
footprint ZAM6228
pins: 1 VDD, 2 GND, 3 A0, 4 RTD1234C, 5 RTD1A, 6 RTD1B , 7 RTD2A, 8 RTD2B, 9 RTD3A, 10 RTD3B, 11 RTD4A, 12 RTD4B, 13 RTD8B, 14 RTD8A, 15 RTD7B, 16 RTD7A, 17 RTD6B, 18 RTD6A, 19 RTD5B, 20 RTD5A, 21 RTD5678C, 22 A1, 23 IIC_SDA, 24 IIC_SCL

## ZCM2x0(2)xD
designator U?
footprint ZCM2x0(2)xD
pins: 1 So-, 2 NC, 3 Sov+, 4 NC, 5 NC, 9 NC, 10 NC, 11 Si+, 12 Si-, 13 NC, 14 NC, 15 NC, 16 NC, 20 NC, 21 NC, 22 NC, 23 Pi+, 24 Pi-

## ZCM2x5(6)xD
designator U?
footprint ZCM2x5(6)xD
pins: 1 So-, 2 Soi+, 3 NC, 4 NC, 5 NC, 9 NC, 10 NC, 11 Si+, 12 Si-, 13 NC, 14 NC, 15 NC, 16 NC, 20 NC, 21 NC, 22 NC, 23 Pi+, 24 Pi-

## ZCM4xxxS
designator U?
footprint ZCM4XXXS
pins: 1 P0+, 2 P0-, 4 Si+, 5 Si-, 6 So+, 7 So-, 8 Vcc+

## ZCM22xxD
designator U?
footprint ZCM22xxD
pins: 1 So-, 2 NC, 3 Sov+, 11 Si+, 12 Si-, 13 Po-, 14 Po+, 15 NC, 16 NC, 23 Pi+, 24 Pi-

## ZCM26xxD
designator U?
footprint ZCM26xxD
pins: 1 So-, 2 NC, 3 Sov+, 11 Si+, 12 Si-, 13 Po-, 14 Po+, 15 NC, 16 NC, 23 Pi+, 24 Pi-

## ZCM1060D
designator U?
footprint ZCM1060D
pins: 1 Iout- (out), 2 Iout+ (out), 3 NC, 7 Iin+ (in), 8 Iin- (in), 9 NC, 10 NC, 14 NC, 15 NC, 16 NC

## ZCM1060S
designator U?
footprint ZCM1060S
pins: 1 Iin+, 2 Iin-, 9 Iout-, 10 Iout-, 11 Iout+, 12 Iout+

## ZCM1060SF
designator U?
footprint ZCM1060SF
pins: 1 Vin, 2 IO, 9 IIN, 10 IIN, 11 VOUT, 12 VOUT

## ZCM1060T
designator U?
footprint ZCM1060T
pins: 1 Iout- (out), 2 Iout+ (out), 3 NC, 7 Iin+ (in), 8 Iin- (in), 9 NC, 10 NC, 14 NC, 15 NC, 16 NC

## ZCM1061DF
designator U?
footprint ZCM1061DF
pins: 1 IO, 2 VDD, 3 VPP+, 4 VPP-

## ZCMFxxxD
designator U?
footprint ZCMFxxxD
pins: 1 G1, 2 G2, 6 VD, 7 GND, 10 B1, 11 B2, 12 B3, 13 Vo+, 14 Vo-, 15 Io+, 16 Io-, 21 Po+, 22 Po-, 23 Fin-, 24 Fin+

## ZCMMxxxD
designator U?
footprint ZCMMxxxD
pins: 1 So-, 2 NC, 3 Sov+, 11 Si+, 12 Si-, 13 Po-, 14 Po+, 15 NC, 16 NC, 23 Pi+, 24 Pi-

## ZCMRxxxxD
designator U?
footprint ZCMRxxxxD
pins: 1 ZA1, 2 ZA2, 3 FB1, 4 FB2, 6 VD, 7 GND, 10 Vo+, 11 NC, 12 Vo-, 13 Io-, 14 NC, 15 Io+, 21 NC, 22 B, 23 B, 24 A

## ZLG1002
designator U?
ZLG1002-HCP90023,SOT-23-6,ZLG
footprint ZLG1002
pins: 1 SVCC, 2 PGND, 3 SGND, 4 SW1, 5 PVCC, 6 SW2

## ZY0FBxxD-2W
designator U?
footprint ZY0FBxxD-2W
pins: 1 AC(L), 2 AC(N), 3 -Vo, 4 +Vo, 5 PG

## ZY0FBxxP-3W
designator U?
footprint ZY0FBxxP-3W
pins: 1 AC(L), 2 AC(N), 3 -Vo, 4 +Vo

## ZY0GAxxCD-5W
designator U?
footprint ZY0GAxxCD-5W
pins: 1 AC(L), 2 AC(N), 3 FG, 4 -Vo, 6 COM, 8 +Vo

## ZY0GBxxD-5W
designator U?
footprint ZY0GBxxD-5W (120426 修改 by kong)
pins: 1 AC(L), 2 AC(N), 3 FG, 4 -Vo, 8 +Vo

## ZY0GBxxD-10W
designator U?
footprint ZY0GBxxD-10W (120426 修改 by kong)
pins: 1 AC(L), 2 AC(N), 3 FG, 5 -Vo, 9 +Vo

## ZY0GBxxD-15W
designator U?
footprint ZY0GBxxD-15W (120426 修改 by kong)
pins: 1 AC(L), 2 AC(N), 3 FG, 5 -Vo, 9 +Vo

## ZY0GBxxD-25W
designator U?
footprint ZY0GBxxD-25W (120426 修改 by kong)
pins: 1 AC(L), 2 AC(N), 3 FG, 5 -Vo, 9 +Vo

## ZY0GBxxP-2W
designator U?
footprint ZY0GBxxP-2W
pins: 1 AC(L), 2 AC(N), 3 -Vo, 4 +Vo

## ZY0GDxxxxDIx-15W
designator U?
footprint ZY0GDxxxxDIx-15W
pins: 1 AC(L), 2 AC(N), 3 FG, 5 -Vo1, 6 +Vo1, 8 -Vo2, 9 +Vo2

## ZY0IFBxxP-3W
designator U?
footprint ZY0IFBxxP-3W
pins: 1 AC(L), 2 AC(N), 3 -Vo, 4 +Vo

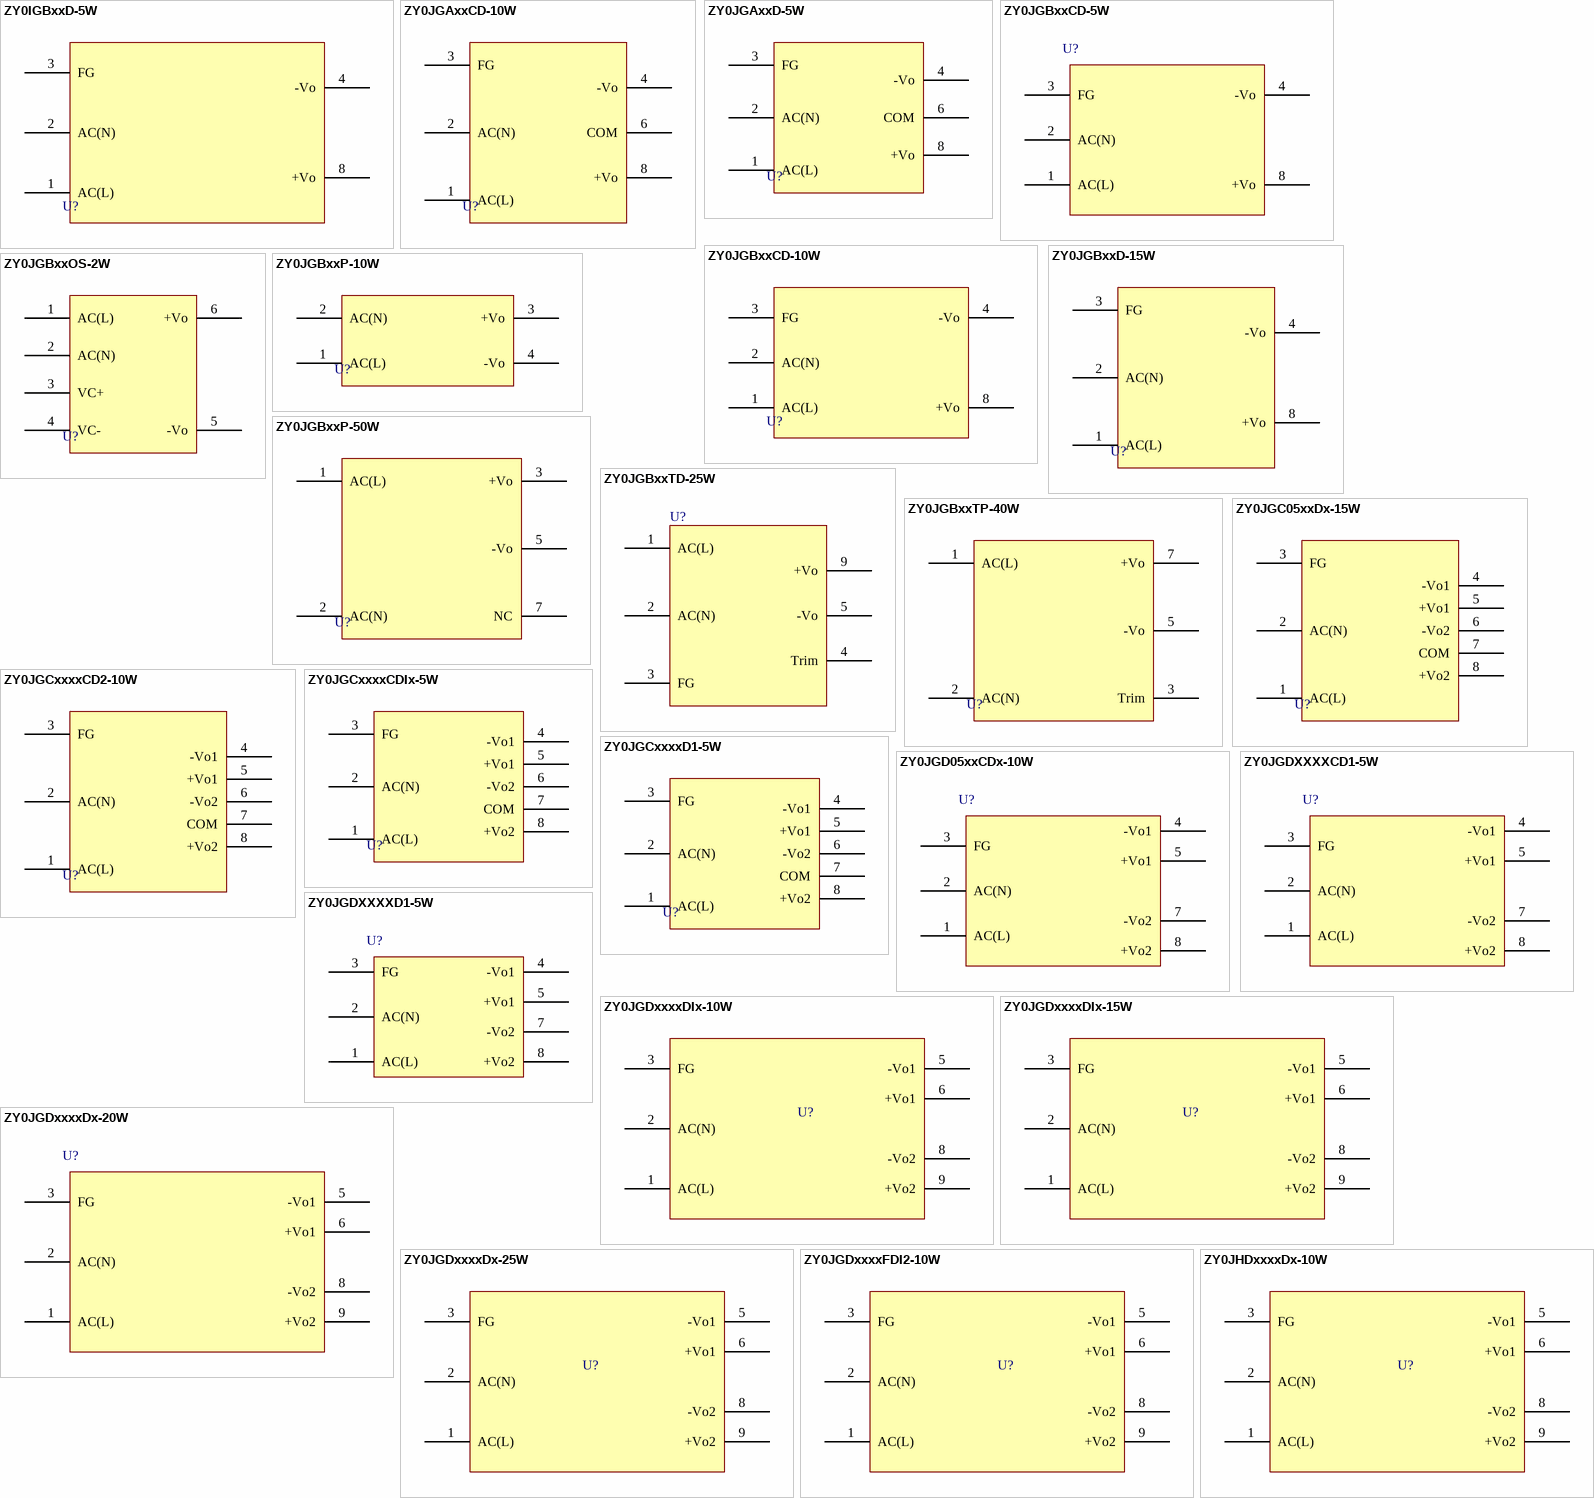
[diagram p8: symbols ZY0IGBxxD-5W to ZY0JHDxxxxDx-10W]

## ZY0IGBxxD-5W
designator U?
footprint ZY0IGBxxD-5W (120426 修改 by kong)
pins: 1 AC(L), 2 AC(N), 3 FG, 4 -Vo, 8 +Vo

## ZY0JGAxxCD-10W
designator U?
footprint ZY0JGAxxCD-10W
pins: 1 AC(L), 2 AC(N), 3 FG, 4 -Vo, 6 COM, 8 +Vo

## ZY0JGAxxD-5W
designator U?
footprint ZY0JGAxxD-5W
pins: 1 AC(L), 2 AC(N), 3 FG, 4 -Vo, 6 COM, 8 +Vo

## ZY0JGBxxCD-5W
designator U?
footprint ZY0JGBxxCD-5W
pins: 1 AC(L), 2 AC(N), 3 FG, 4 -Vo, 8 +Vo

## ZY0JGBxxCD-10W
designator U?
footprint ZY0JGBxxCD-10W
pins: 1 AC(L), 2 AC(N), 3 FG, 4 -Vo, 8 +Vo

## ZY0JGBxxD-15W
designator U?
footprint ZY0JGBxxD-15W
pins: 1 AC(L), 2 AC(N), 3 FG, 4 -Vo, 8 +Vo

## ZY0JGBxxOS-2W
designator U?
footprint ZY0JGBxxOS-2W
pins: 1 AC(L), 2 AC(N), 3 VC+, 4 VC-, 5 -Vo, 6 +Vo

## ZY0JGBxxP-10W
designator U?
footprint ZY0JGBxxP-10W
pins: 1 AC(L), 2 AC(N), 3 +Vo, 4 -Vo

## ZY0JGBxxP-50W
designator U?
footprint ZY0JGBxxP-50W
pins: 1 AC(L), 2 AC(N), 3 +Vo, 5 -Vo, 7 NC

## ZY0JGBxxTD-25W
designator U?
footprint ZY0JGBxxTD-25W
pins: 1 AC(L), 2 AC(N), 3 FG, 4 Trim, 5 -Vo, 9 +Vo

## ZY0JGBxxTP-40W
designator U?
footprint ZY0JGBxxTP-40W
pins: 1 AC(L), 2 AC(N), 3 Trim, 5 -Vo, 7 +Vo

## ZY0JGC05xxDx-15W
designator U?
footprint ZY0JGC05xxDx-15W
pins: 1 AC(L), 2 AC(N), 3 FG, 4 -Vo1, 5 +Vo1, 6 -Vo2, 7 COM, 8 +Vo2

## ZY0JGCxxxxCD2-10W
designator U?
footprint ZY0JGCxxxxCD2-10W
pins: 1 AC(L), 2 AC(N), 3 FG, 4 -Vo1, 5 +Vo1, 6 -Vo2, 7 COM, 8 +Vo2

## ZY0JGCxxxxCDIx-5W
designator U?
footprint ZY0JGCxxxxCDIx-5W
pins: 1 AC(L), 2 AC(N), 3 FG, 4 -Vo1, 5 +Vo1, 6 -Vo2, 7 COM, 8 +Vo2

## ZY0JGCxxxxD1-5W
designator U?
footprint ZY0JGCxxxxD1-5W
pins: 1 AC(L), 2 AC(N), 3 FG, 4 -Vo1, 5 +Vo1, 6 -Vo2, 7 COM, 8 +Vo2

## ZY0JGD05xxCDx-10W
designator U?
footprint ZY0JGD05xxCDx-10W
pins: 1 AC(L), 2 AC(N), 3 FG, 4 -Vo1, 5 +Vo1, 7 -Vo2, 8 +Vo2

## ZY0JGDXXXXCD1-5W
designator U?
footprint ZY0JGDxxxxCD1-5W
pins: 1 AC(L), 2 AC(N), 3 FG, 4 -Vo1, 5 +Vo1, 7 -Vo2, 8 +Vo2

## ZY0JGDXXXXD1-5W
designator U?
footprint ZY0JGDXXXXD1-5W
pins: 1 AC(L), 2 AC(N), 3 FG, 4 -Vo1, 5 +Vo1, 7 -Vo2, 8 +Vo2

## ZY0JGDxxxxDIx-10W
designator U?
footprint ZY0JGDxxxxDIx-10W
pins: 1 AC(L), 2 AC(N), 3 FG, 5 -Vo1, 6 +Vo1, 8 -Vo2, 9 +Vo2

## ZY0JGDxxxxDIx-15W
designator U?
footprint ZY0JGDxxxxDIx-15W
pins: 1 AC(L), 2 AC(N), 3 FG, 5 -Vo1, 6 +Vo1, 8 -Vo2, 9 +Vo2

## ZY0JGDxxxxDx-20W
designator U?
footprint ZY0JGDxxxxDx-20W
pins: 1 AC(L), 2 AC(N), 3 FG, 5 -Vo1, 6 +Vo1, 8 -Vo2, 9 +Vo2

## ZY0JGDxxxxDx-25W
designator U?
footprint ZY0JGDxxxxDx-25W
pins: 1 AC(L), 2 AC(N), 3 FG, 5 -Vo1, 6 +Vo1, 8 -Vo2, 9 +Vo2

## ZY0JGDxxxxFDI2-10W
designator U?
footprint ZY0JGDxxxxFDI2-10W
pins: 1 AC(L), 2 AC(N), 3 FG, 5 -Vo1, 6 +Vo1, 8 -Vo2, 9 +Vo2

## ZY0JHDxxxxDx-10W
designator U?
footprint ZY0JHDxxxxDx-10W
pins: 1 AC(L), 2 AC(N), 3 FG, 5 -Vo1, 6 +Vo1, 8 -Vo2, 9 +Vo2

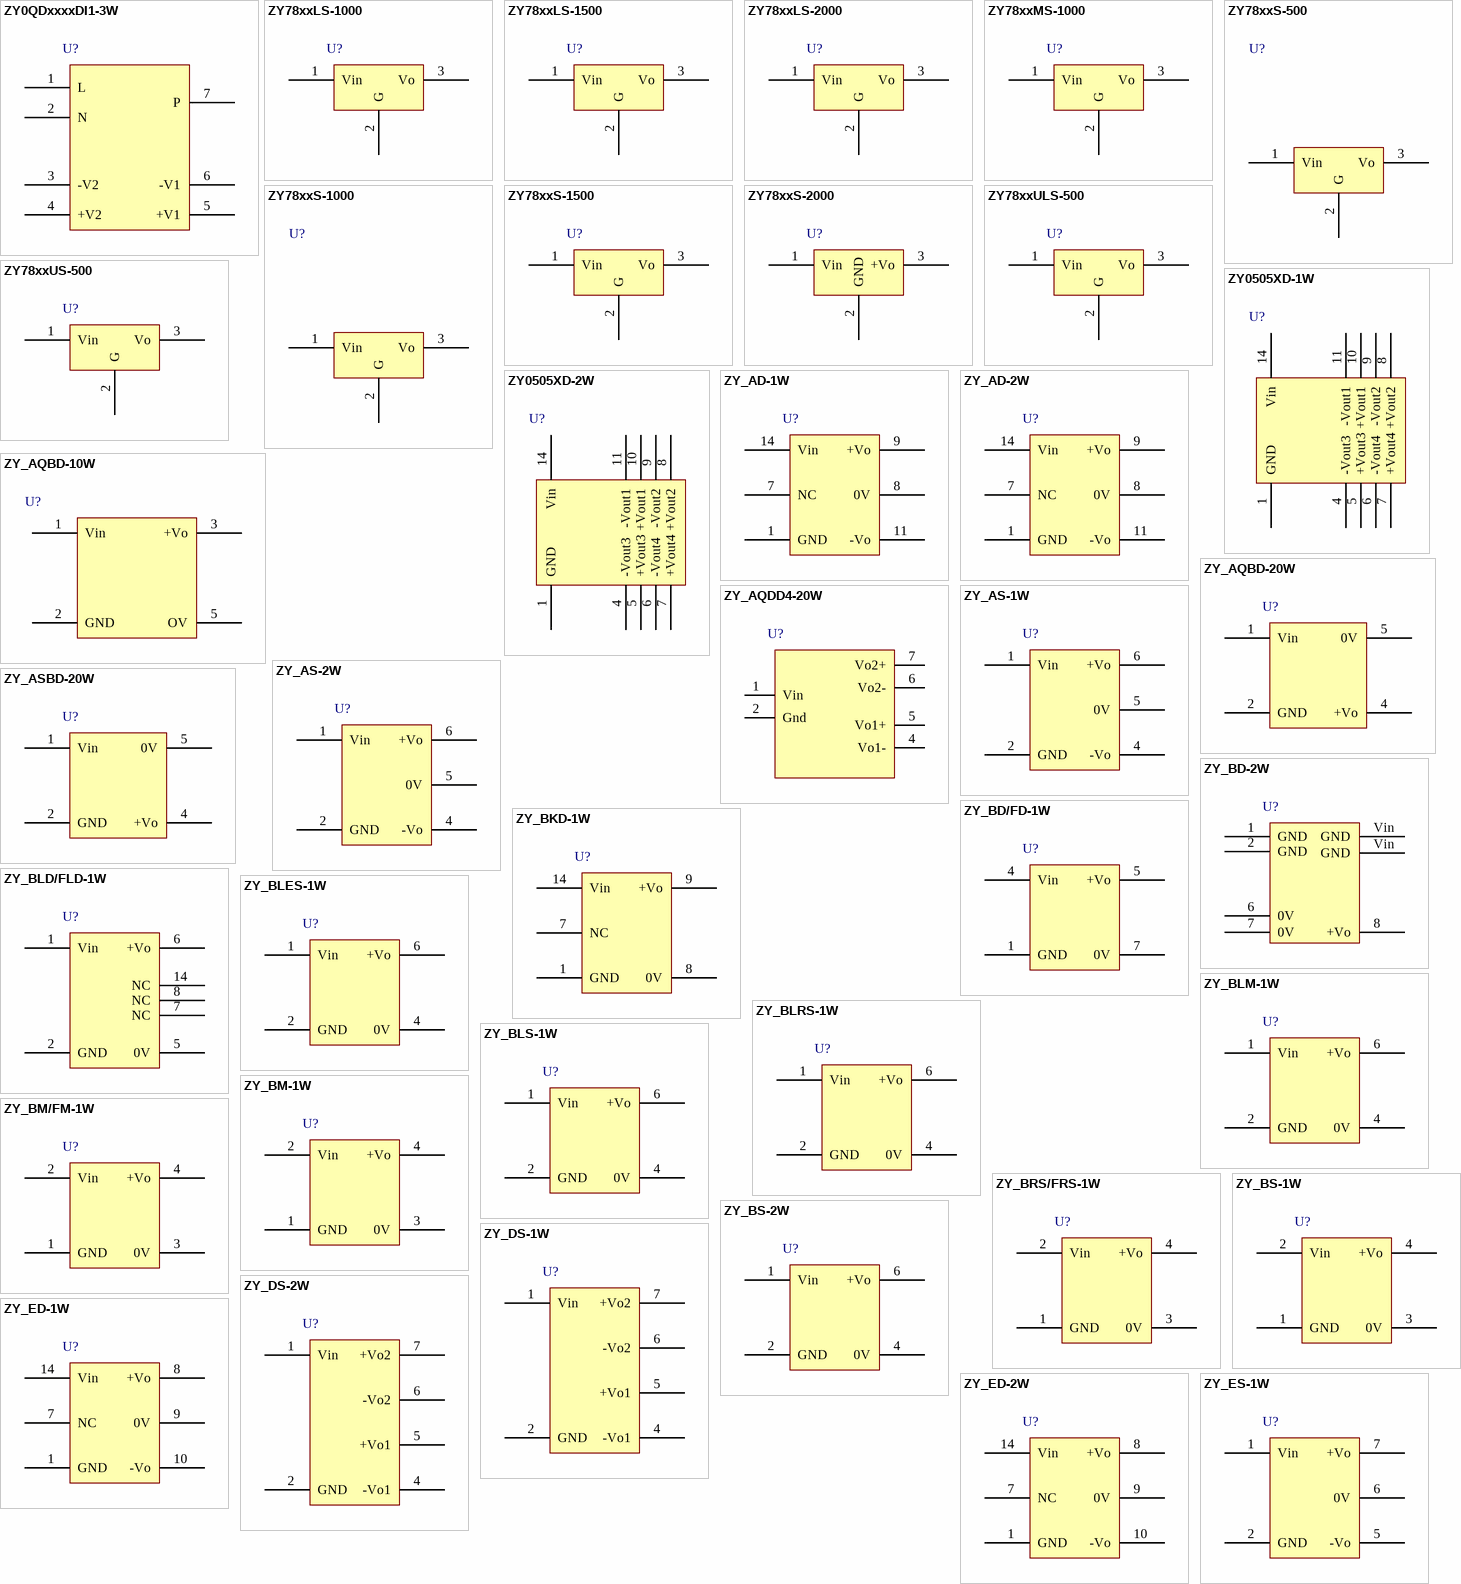
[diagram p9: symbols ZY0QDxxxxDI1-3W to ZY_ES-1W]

## ZY0QDxxxxDI1-3W
designator U?
footprint ZY0QDxxxxDI1-3W
pins: 1 L, 2 N, 3 -V2, 4 +V2, 5 +V1, 6 -V1, 7 P

## ZY78xxLS-1000
designator U?
footprint ZY78xxLS-1000
pins: 1 Vin, 2 G, 3 Vo

## ZY78xxLS-1500
designator U?
footprint ZY78xxLS-1500
pins: 1 Vin, 2 G, 3 Vo

## ZY78xxLS-2000
designator U?
footprint ZY78xxLS-2000
pins: 1 Vin, 2 G, 3 Vo

## ZY78xxMS-1000
designator U?
footprint ZY78xxMS-1000
pins: 1 Vin, 2 G, 3 Vo

## ZY78xxS-500
designator U?
footprint ZY78xxS-500
pins: 1 Vin, 2 G, 3 Vo

## ZY78xxS-1000
designator U?
footprint ZY78xxS-1000
pins: 1 Vin, 2 G, 3 Vo

## ZY78xxS-1500
designator U?
footprint ZY78xxS-1500
pins: 1 Vin, 2 G, 3 Vo

## ZY78xxS-2000
designator U?
footprint ZY78xxS-2000
pins: 1 Vin, 2 GND, 3 +Vo

## ZY78xxULS-500
designator U?
footprint ZY78xxULS-500
pins: 1 Vin, 2 G, 3 Vo

## ZY78xxUS-500
designator U?
footprint ZY78xxUS-500
pins: 1 Vin, 2 G, 3 Vo

## ZY0505XD-1W
designator U?
footprint ZY0505XD-1W
pins: 1 GND, 4 -Vout3, 5 +Vout3, 6 -Vout4, 7 +Vout4, 8 +Vout2, 9 -Vout2, 10 +Vout1, 11 -Vout1, 14 Vin

## ZY0505XD-2W
designator U?
footprint ZY0505XD-2W (Footprint not found)
pins: 1 GND, 4 -Vout3, 5 +Vout3, 6 -Vout4, 7 +Vout4, 8 +Vout2, 9 -Vout2, 10 +Vout1, 11 -Vout1, 14 Vin

## ZY_AD-1W
designator U?
footprint ZY_AD-1W
pins: 1 GND, 7 NC, 8 0V, 9 +Vo, 11 -Vo, 14 Vin

## ZY_AD-2W
designator U?
footprint ZY_AD-2W
pins: 1 GND, 7 NC, 8 0V, 9 +Vo, 11 -Vo, 14 Vin

## ZY_AQBD-10W
designator U?
footprint ZY_AQBD-10W
pins: 1 Vin, 2 GND, 3 +Vo, 5 OV

## ZY_AQBD-20W
designator U?
footprint ZY_AQBD-20W
pins: 1 Vin, 2 GND, 4 +Vo, 5 0V

## ZY_AQDD4-20W
designator U?
footprint ZY_AQDD4-20W
pins: 1 Vin, 2 Gnd, 4 Vo1-, 5 Vo1+, 6 Vo2-, 7 Vo2+

## ZY_AS-1W
designator U?
footprint ZY_AS-1W (定压输入隔离非稳压正、负双输出)
pins: 1 Vin, 2 GND, 4 -Vo, 5 0V, 6 +Vo

## ZY_AS-2W
designator U?
footprint ZY_AS-2W (定压输入隔离非稳压正、负双输出)
pins: 1 Vin, 2 GND, 4 -Vo, 5 0V, 6 +Vo

## ZY_ASBD-20W
designator U?
footprint ZY_ASBD-20W
pins: 1 Vin, 2 GND, 4 +Vo, 5 0V

## ZY_BD-2W
designator U?
footprint ZY_BD-2W
pins: 1 GND, 2 GND, 6 0V, 7 0V, 8 +Vo, Vin GND, Vin GND

## ZY_BD/FD-1W
designator U?
footprint ZY_BD/FD-1W (定压输入隔离非稳压单输出)
pins: 1 GND, 4 Vin, 5 +Vo, 7 0V

## ZY_BKD-1W
designator U?
footprint ZY_BKD-1W
pins: 1 GND, 7 NC, 8 0V, 9 +Vo, 14 Vin

## ZY_BLD/FLD-1W
designator U?
footprint ZY_BLD/FLD-1W (定压输入隔离非稳压单输出)
pins: 1 Vin, 2 GND, 5 0V, 6 +Vo, 7 NC, 8 NC, 14 NC

## ZY_BLES-1W
designator U?
footprint ZY_BLES-1W
pins: 1 Vin, 2 GND, 4 0V, 6 +Vo

## ZY_BLM-1W
designator U?
footprint ZY_BLM-1W
pins: 1 Vin, 2 GND, 4 0V, 6 +Vo

## ZY_BLRS-1W
designator U?
footprint ZY_BLRS-1W
pins: 1 Vin, 2 GND, 4 0V, 6 +Vo

## ZY_BLS-1W
designator U?
footprint ZY_BLS-1W (定压输入隔离非稳压单输出)
pins: 1 Vin, 2 GND, 4 0V, 6 +Vo

## ZY_BM-1W
designator U?
footprint ZY_BM-1W (定压输入隔离非稳压单输出)
pins: 1 GND, 2 Vin, 3 0V, 4 +Vo

## ZY_BM/FM-1W
designator U?
footprint ZY_BM/FM-1W
pins: 1 GND, 2 Vin, 3 0V, 4 +Vo

## ZY_BRS/FRS-1W
designator U?
footprint ZY_BRS/FRS-1W
pins: 1 GND, 2 Vin, 3 0V, 4 +Vo

## ZY_BS-1W
designator U?
footprint ZY_BS-1W (定压输入隔离非稳压单输出)
pins: 1 GND, 2 Vin, 3 0V, 4 +Vo

## ZY_BS-2W
designator U?
footprint ZY_BS-2W (定压输入隔离非稳压单输出)
pins: 1 Vin, 2 GND, 4 0V, 6 +Vo

## ZY_DS-1W
designator U?
footprint ZY_DS-1W
pins: 1 Vin, 2 GND, 4 -Vo1, 5 +Vo1, 6 -Vo2, 7 +Vo2

## ZY_DS-2W
designator U?
footprint ZY_DS-2W (定压输入隔离非稳压双输出)
pins: 1 Vin, 2 GND, 4 -Vo1, 5 +Vo1, 6 -Vo2, 7 +Vo2

## ZY_ED-1W
designator U?
footprint ZY_ED-1W (定压输入隔离非稳压正、负输出)
pins: 1 GND, 7 NC, 8 +Vo, 9 0V, 10 -Vo, 14 Vin

## ZY_ED-2W
designator U?
footprint ZY_ED-2W
pins: 1 GND, 7 NC, 8 +Vo, 9 0V, 10 -Vo, 14 Vin

## ZY_ES-1W
designator U?
footprint ZY_ES-1W (定压输入隔离非稳压正、负输出)
pins: 1 Vin, 2 GND, 5 -Vo, 6 0V, 7 +Vo

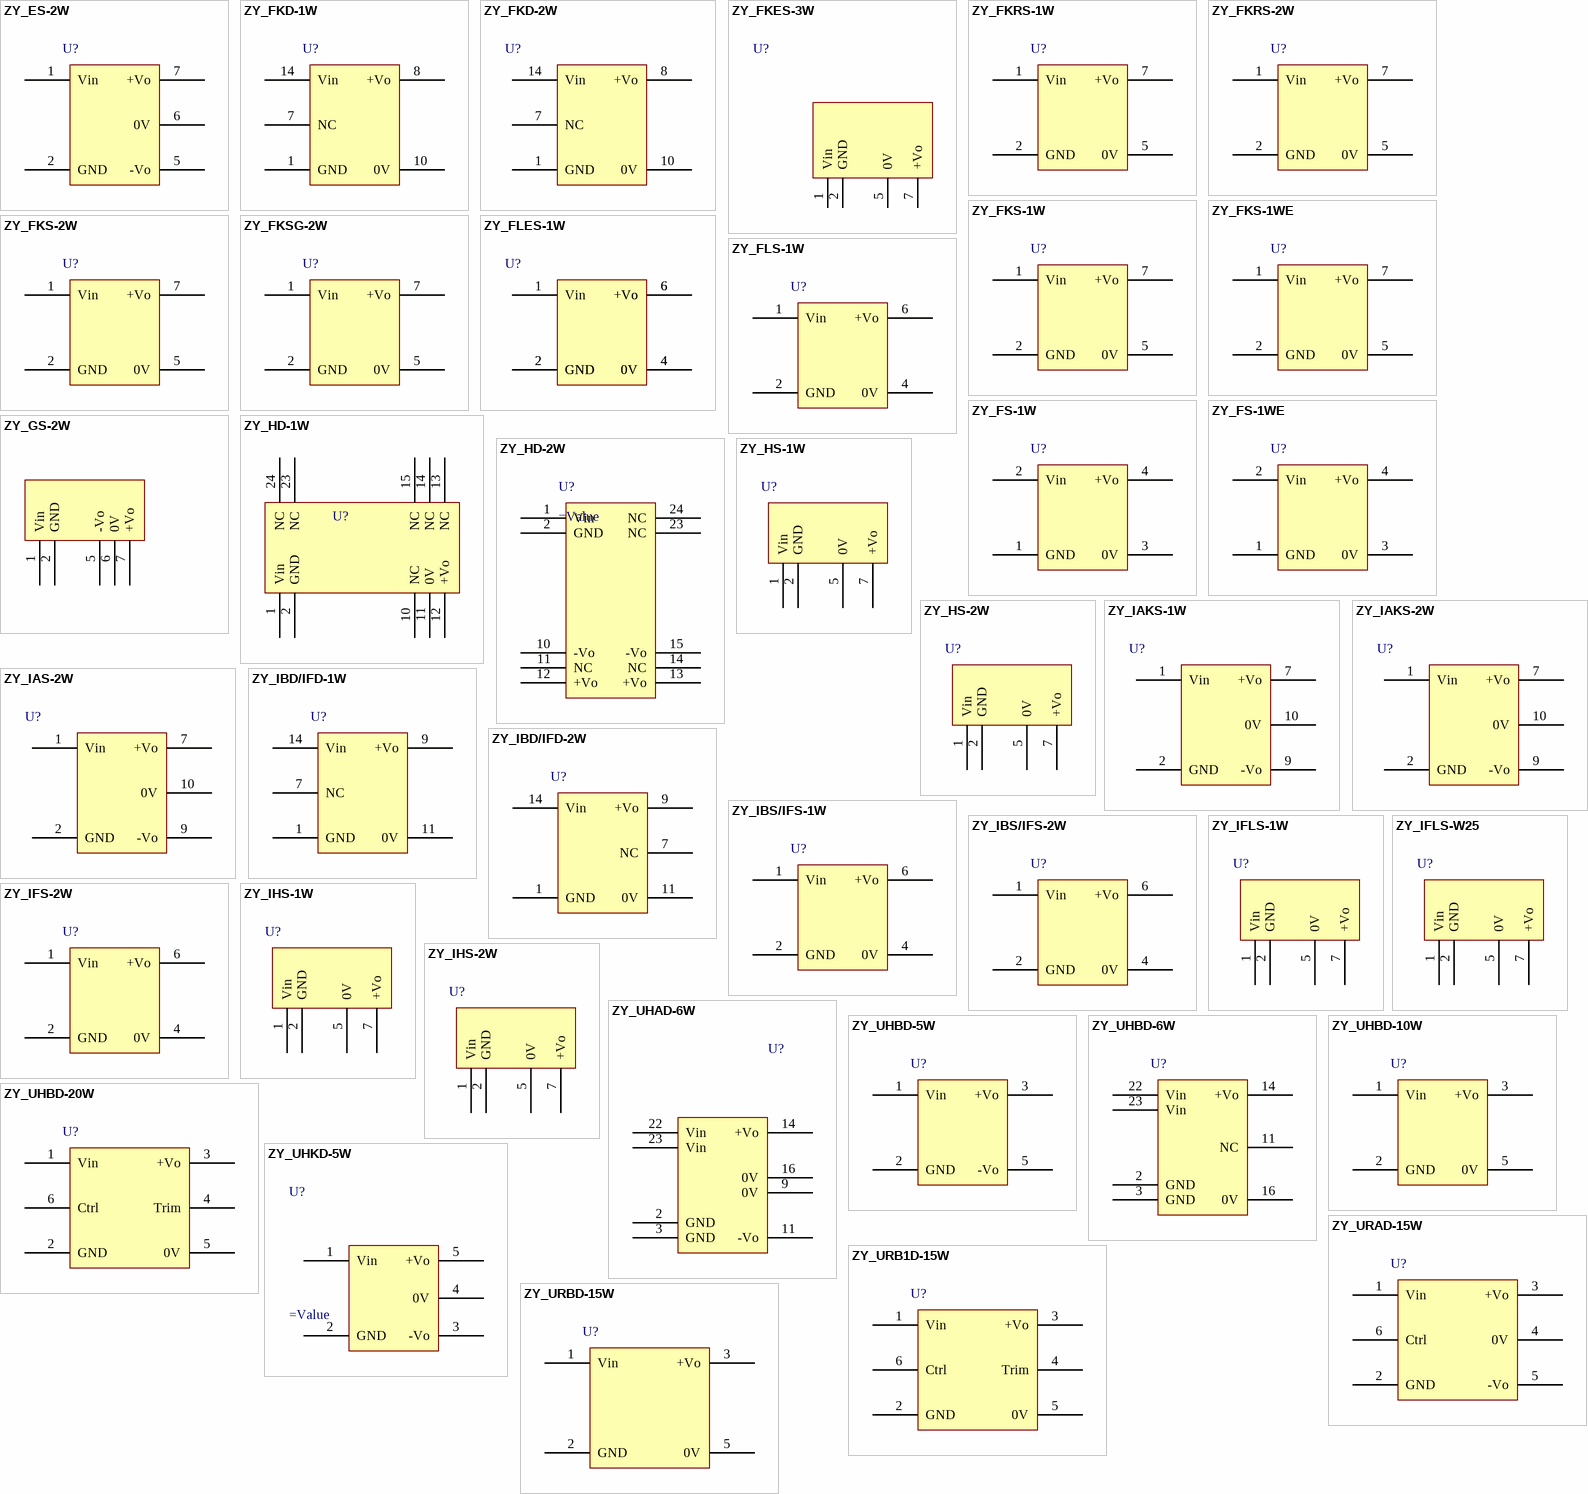
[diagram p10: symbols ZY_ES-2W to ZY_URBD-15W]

## ZY_ES-2W
designator U?
footprint ZY_ES-2W (定压输入隔离非稳压双输出)
pins: 1 Vin, 2 GND, 5 -Vo, 6 0V, 7 +Vo

## ZY_FKD-1W
designator U?
footprint ZY_FKD-1W
pins: 1 GND, 7 NC, 8 +Vo, 10 0V, 14 Vin

## ZY_FKD-2W
designator U?
footprint ZY_FKD-2W
pins: 1 GND, 7 NC, 8 +Vo, 10 0V, 14 Vin

## ZY_FKES-3W
designator U?
footprint ZY_FKES-3W
pins: 1 Vin, 2 GND, 5 0V, 7 +Vo

## ZY_FKRS-1W
designator U?
footprint ZY_FKRS-1W
pins: 1 Vin, 2 GND, 5 0V, 7 +Vo

## ZY_FKRS-2W
designator U?
footprint ZY_FKRS-2W
pins: 1 Vin, 2 GND, 5 0V, 7 +Vo

## ZY_FKS-1W
designator U?
footprint ZY_FKS-1W
pins: 1 Vin, 2 GND, 5 0V, 7 +Vo

## ZY_FKS-1WE
designator U?
footprint ZY_FKS-1WE
pins: 1 Vin, 2 GND, 5 0V, 7 +Vo

## ZY_FKS-2W
designator U?
footprint ZY_FKS-2W (定压输入隔离非稳压单输出)
pins: 1 Vin, 2 GND, 5 0V, 7 +Vo

## ZY_FKSG-2W
designator U?
footprint ZY_FKSG-2W (Footprint not found)
pins: 1 Vin, 2 GND, 5 0V, 7 +Vo

## ZY_FLES-1W
designator U?
footprint ZY_FLES-1W
pins: 1 Vin, 2 GND, 2 GND, 4 0V, 4 0V, 6 +Vo, 6 +Vo

## ZY_FLS-1W
designator U?
footprint ZY_FLS-1W
pins: 1 Vin, 2 GND, 4 0V, 6 +Vo

## ZY_FS-1W
designator U?
footprint ZY_FS-1W (定压输入隔离非稳压单输出)
pins: 1 GND, 2 Vin, 3 0V, 4 +Vo

## ZY_FS-1WE
designator U?
footprint ZY_FS-1WE (定压输入隔离非稳压单输出)
pins: 1 GND, 2 Vin, 3 0V, 4 +Vo

## ZY_GS-2W
designator U?
footprint ZY_GS-2W
pins: 1 Vin, 2 GND, 5 -Vo, 6 0V, 7 +Vo

## ZY_HD-1W
designator U?
footprint ZY_HD-1W
pins: 1 Vin, 2 GND, 10 NC, 11 0V, 12 +Vo, 13 NC, 14 NC, 15 NC, 23 NC, 24 NC

## ZY_HD-2W
designator U?
footprint ZY_HD-2W
pins: 1 Vin, 2 GND, 10 -Vo, 11 NC, 12 +Vo, 13 +Vo, 14 NC, 15 -Vo, 23 NC, 24 NC

## ZY_HS-1W
designator U?
footprint ZY_HS-1W
pins: 1 Vin, 2 GND, 5 0V, 7 +Vo

## ZY_HS-2W
designator U?
footprint ZY_HS-2W
pins: 1 Vin, 2 GND, 5 0V, 7 +Vo

## ZY_IAKS-1W
designator U?
footprint ZY_IAKS-1W (定压输入隔离稳压双输出)
pins: 1 Vin, 2 GND, 7 +Vo, 9 -Vo, 10 0V

## ZY_IAKS-2W
designator U?
footprint ZY_IAKS-2W
pins: 1 Vin, 2 GND, 7 +Vo, 9 -Vo, 10 0V

## ZY_IAS-2W
designator U?
footprint ZY_IAS-2W
pins: 1 Vin, 2 GND, 7 +Vo, 9 -Vo, 10 0V

## ZY_IBD/IFD-1W
designator U?
footprint ZY_IBD/IFD-1W
pins: 1 GND, 7 NC, 9 +Vo, 11 0V, 14 Vin

## ZY_IBD/IFD-2W
designator U?
footprint ZY_IBD/IFD-2W
pins: 1 GND, 7 NC, 9 +Vo, 11 0V, 14 Vin

## ZY_IBS/IFS-1W
designator U?
footprint ZY_IBS/IFS-1W (定压输入隔离稳压单输出)
pins: 1 Vin, 2 GND, 4 0V, 6 +Vo

## ZY_IBS/IFS-2W
designator U?
footprint ZY_IBS/IFS-2W
pins: 1 Vin, 2 GND, 4 0V, 6 +Vo

## ZY_IFLS-1W
designator U?
footprint ZY_IFLS-1W
pins: 1 Vin, 2 GND, 5 0V, 7 +Vo

## ZY_IFLS-W25
designator U?
footprint ZY_IFLS-W25
pins: 1 Vin, 2 GND, 5 0V, 7 +Vo

## ZY_IFS-2W
designator U?
footprint ZY_IFS-2W
pins: 1 Vin, 2 GND, 4 0V, 6 +Vo

## ZY_IHS-1W
designator U?
footprint ZY_IHS-1W
pins: 1 Vin, 2 GND, 5 0V, 7 +Vo

## ZY_IHS-2W
designator U?
footprint ZY_IHS-2W
pins: 1 Vin, 2 GND, 5 0V, 7 +Vo

## ZY_UHAD-6W
designator U?
footprint ZY_UHAD-6W
pins: 2 GND, 3 GND, 9 0V, 11 -Vo, 14 +Vo, 16 0V, 22 Vin, 23 Vin

## ZY_UHBD-5W
designator U?
footprint ZY_UHBD-5W
pins: 1 Vin, 2 GND, 3 +Vo, 5 -Vo

## ZY_UHBD-6W
designator U?
footprint ZY_UHBD-6W
pins: 2 GND, 3 GND, 11 NC, 14 +Vo, 16 0V, 22 Vin, 23 Vin

## ZY_UHBD-10W
designator U?
footprint ZY_UHBD-10W
pins: 1 Vin, 2 GND, 3 +Vo, 5 0V

## ZY_UHBD-20W
designator U?
footprint ZY_UHBD-20W
pins: 1 Vin, 2 GND, 3 +Vo, 4 Trim, 5 0V, 6 Ctrl

## ZY_UHKD-5W
designator U?
footprint ZY_UHKD-5W
pins: 1 Vin, 2 GND, 3 -Vo, 4 0V, 5 +Vo

## ZY_URAD-15W
designator U?
footprint ZY_URAD-15W
pins: 1 Vin, 2 GND, 3 +Vo, 4 0V, 5 -Vo, 6 Ctrl

## ZY_URB1D-15W
designator U?
footprint ZY_URB1D-15W
pins: 1 Vin, 2 GND, 3 +Vo, 4 Trim, 5 0V, 6 Ctrl

## ZY_URBD-15W
designator U?
footprint ZY_URBD-15W
pins: 1 Vin, 2 GND, 3 +Vo, 5 0V

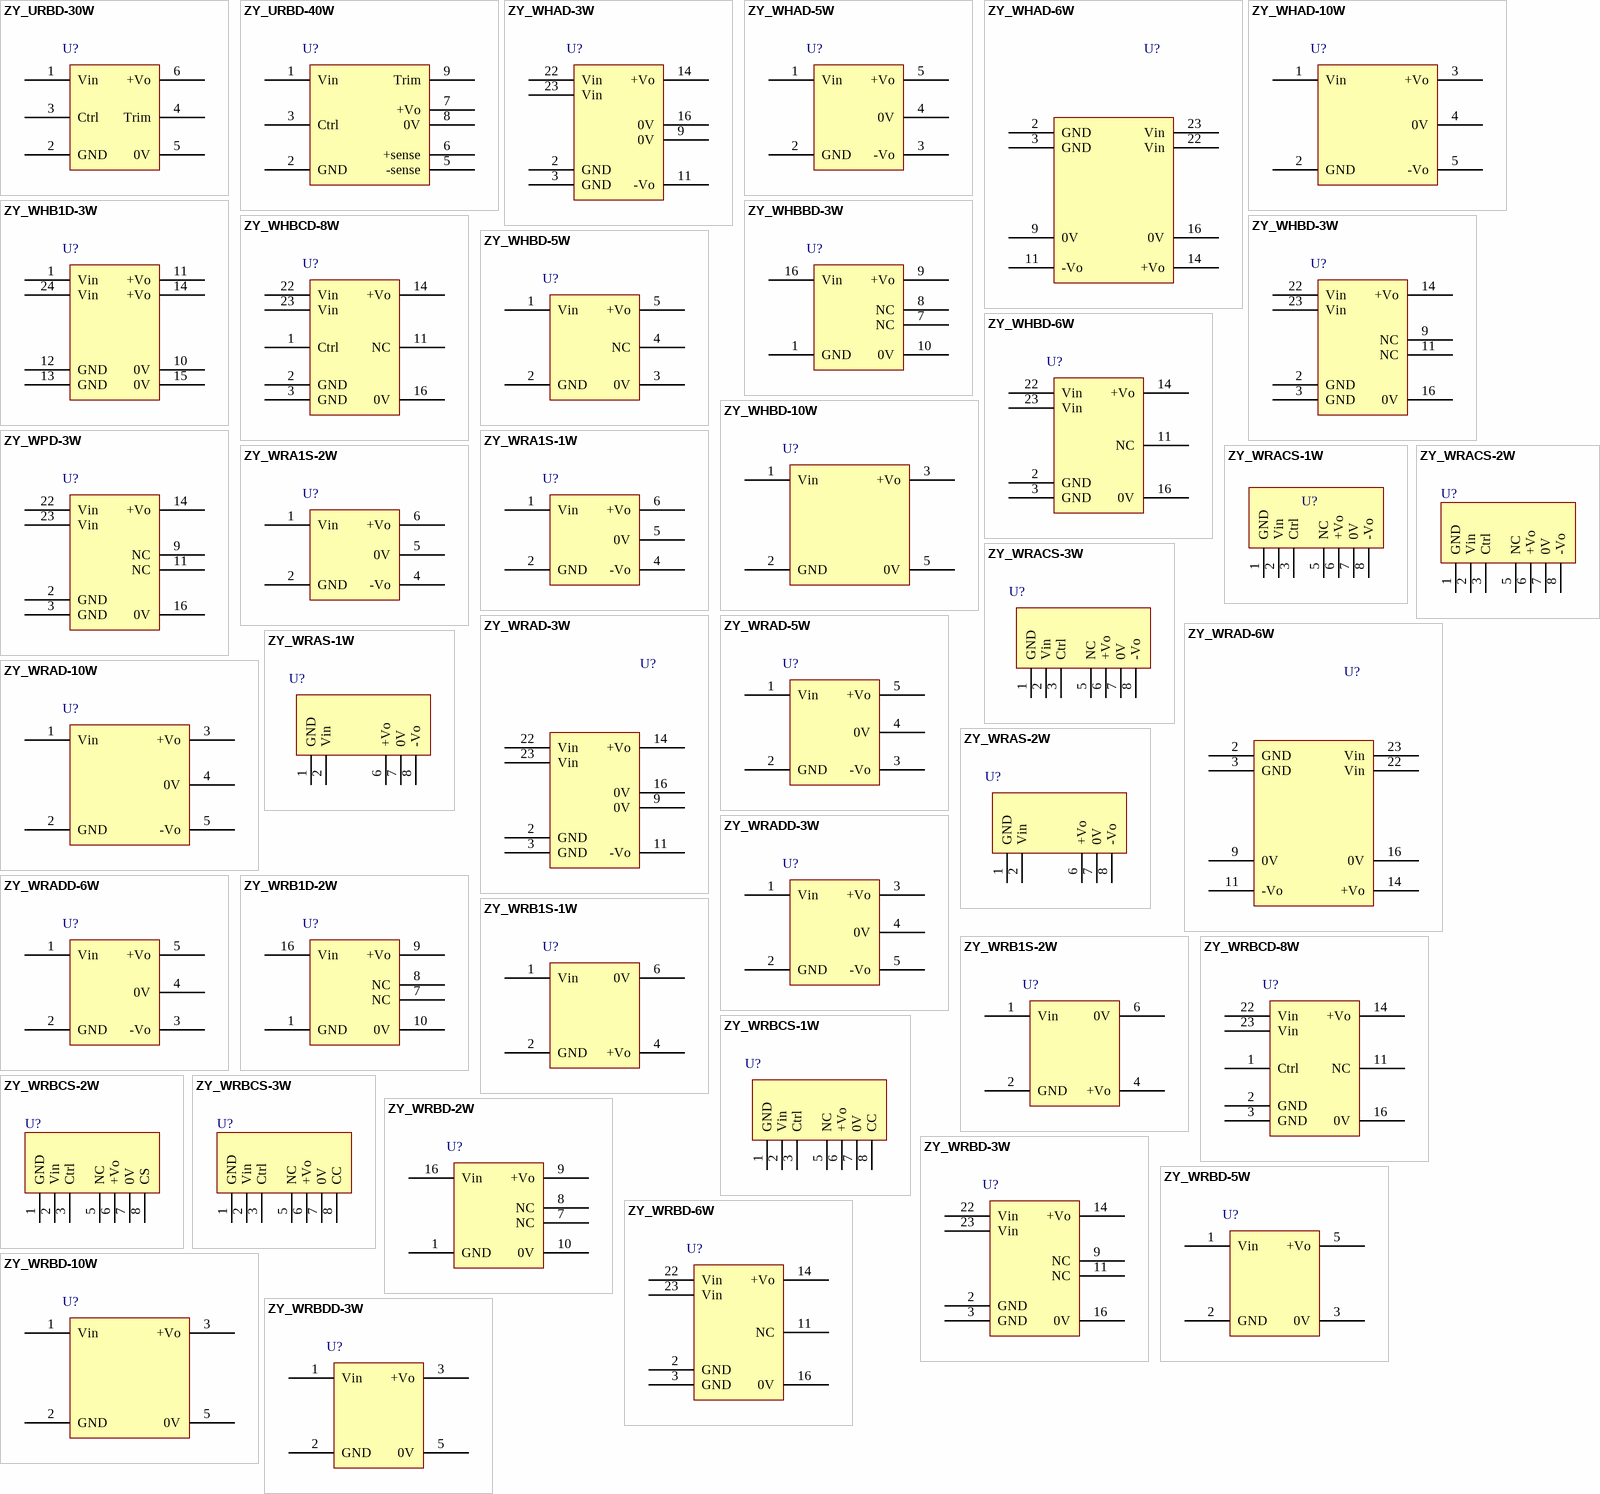
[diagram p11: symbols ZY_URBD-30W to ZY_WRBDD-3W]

## ZY_URBD-30W
designator U?
footprint ZY_URBD-30W
pins: 1 Vin, 2 GND, 3 Ctrl, 4 Trim, 5 0V, 6 +Vo

## ZY_URBD-40W
designator U?
footprint ZY_URBD-40W
pins: 1 Vin, 2 GND, 3 Ctrl, 5 -sense, 6 +sense, 7 +Vo, 8 0V, 9 Trim

## ZY_WHAD-3W
designator U?
footprint ZY_WHAD-3W (宽压输入隔离稳压双输出电源模块)
pins: 2 GND, 3 GND, 9 0V, 11 -Vo, 14 +Vo, 16 0V, 22 Vin, 23 Vin

## ZY_WHAD-5W
designator U?
footprint ZY_WHAD-5W
pins: 1 Vin, 2 GND, 3 -Vo, 4 0V, 5 +Vo

## ZY_WHAD-6W
designator U?
footprint ZY_WHAD-6W
pins: 2 GND, 3 GND, 9 0V, 11 -Vo, 14 +Vo, 16 0V, 22 Vin, 23 Vin

## ZY_WHAD-10W
designator U?
footprint ZY_WHAD-10W
pins: 1 Vin, 2 GND, 3 +Vo, 4 0V, 5 -Vo

## ZY_WHB1D-3W
designator U?
footprint ZY_WHB1D-3W
pins: 1 Vin, 10 0V, 11 +Vo, 12 GND, 13 GND, 14 +Vo, 15 0V, 24 Vin

## ZY_WHBBD-3W
designator U?
footprint ZY_WHBBD-3W
pins: 1 GND, 7 NC, 8 NC, 9 +Vo, 10 0V, 16 Vin

## ZY_WHBCD-8W
designator U?
footprint ZY_WHBCD-8W
pins: 1 Ctrl, 2 GND, 3 GND, 11 NC, 14 +Vo, 16 0V, 22 Vin, 23 Vin

## ZY_WHBD-3W
designator U?
footprint ZY_WHBD-3W (宽压输入隔离稳压单输出电源模块)
pins: 2 GND, 3 GND, 9 NC, 11 NC, 14 +Vo, 16 0V, 22 Vin, 23 Vin

## ZY_WHBD-5W
designator U?
footprint ZY_WHBD-5W
pins: 1 Vin, 2 GND, 3 0V, 4 NC, 5 +Vo

## ZY_WHBD-6W
designator U?
footprint ZY_WHBD-6W
pins: 2 GND, 3 GND, 11 NC, 14 +Vo, 16 0V, 22 Vin, 23 Vin

## ZY_WHBD-10W
designator U?
footprint ZY_WHBD-10W
pins: 1 Vin, 2 GND, 3 +Vo, 5 0V

## ZY_WPD-3W
designator U?
footprint ZY_WPD-3W (宽压输入非隔离稳压单输出)
pins: 2 GND, 3 GND, 9 NC, 11 NC, 14 +Vo, 16 0V, 22 Vin, 23 Vin

## ZY_WRA1S-1W
designator U?
footprint ZY_WRA1S-1W
pins: 1 Vin, 2 GND, 4 -Vo, 5 0V, 6 +Vo

## ZY_WRA1S-2W
designator U?
footprint ZY_WRA1S-2W
pins: 1 Vin, 2 GND, 4 -Vo, 5 0V, 6 +Vo

## ZY_WRACS-1W
designator U?
footprint ZY_WRACS-1W
pins: 1 GND, 2 Vin, 3 Ctrl, 5 NC, 6 +Vo, 7 0V, 8 -Vo

## ZY_WRACS-2W
designator U?
footprint ZY_WRACS-2W
pins: 1 GND, 2 Vin, 3 Ctrl, 5 NC, 6 +Vo, 7 0V, 8 -Vo

## ZY_WRACS-3W
designator U?
footprint ZY_WRACS-3W
pins: 1 GND, 2 Vin, 3 Ctrl, 5 NC, 6 +Vo, 7 0V, 8 -Vo

## ZY_WRAD-3W
designator U?
footprint ZY_WRAD-3W
pins: 2 GND, 3 GND, 9 0V, 11 -Vo, 14 +Vo, 16 0V, 22 Vin, 23 Vin

## ZY_WRAD-5W
designator U?
footprint ZY_WRAD-5W
pins: 1 Vin, 2 GND, 3 -Vo, 4 0V, 5 +Vo

## ZY_WRAD-6W
designator U?
footprint ZY_WRAD-6W
pins: 2 GND, 3 GND, 9 0V, 11 -Vo, 14 +Vo, 16 0V, 22 Vin, 23 Vin

## ZY_WRAD-10W
designator U?
footprint ZY_WRAD-10W
pins: 1 Vin, 2 GND, 3 +Vo, 4 0V, 5 -Vo

## ZY_WRADD-3W
designator U?
footprint ZY_WRADD-3W
pins: 1 Vin, 2 GND, 3 +Vo, 4 0V, 5 -Vo

## ZY_WRADD-6W
designator U?
footprint ZY_WRADD-6W
pins: 1 Vin, 2 GND, 3 -Vo, 4 0V, 5 +Vo

## ZY_WRAS-1W
designator U?
footprint ZY_WRAS-1W
pins: 1 GND, 2 Vin, 6 +Vo, 7 0V, 8 -Vo

## ZY_WRAS-2W
designator U?
footprint ZY_WRAS-2W
pins: 1 GND, 2 Vin, 6 +Vo, 7 0V, 8 -Vo

## ZY_WRB1D-2W
designator U?
footprint ZY_WRB1D-2W
pins: 1 GND, 7 NC, 8 NC, 9 +Vo, 10 0V, 16 Vin

## ZY_WRB1S-1W
designator U?
footprint ZY_WRB1S-1W
pins: 1 Vin, 2 GND, 4 +Vo, 6 0V

## ZY_WRB1S-2W
designator U?
footprint ZY_WRB1S-2W
pins: 1 Vin, 2 GND, 4 +Vo, 6 0V

## ZY_WRBCD-8W
designator U?
footprint ZY_WRBCD-8W
pins: 1 Ctrl, 2 GND, 3 GND, 11 NC, 14 +Vo, 16 0V, 22 Vin, 23 Vin

## ZY_WRBCS-1W
designator U?
footprint ZY_WRBCS-1W
pins: 1 GND, 2 Vin, 3 Ctrl, 5 NC, 6 +Vo, 7 0V, 8 CC

## ZY_WRBCS-2W
designator U?
footprint ZY_WRBCS-2W
pins: 1 GND, 2 Vin, 3 Ctrl, 5 NC, 6 +Vo, 7 0V, 8 CS

## ZY_WRBCS-3W
designator U?
footprint ZY_WRBCS-3W
pins: 1 GND, 2 Vin, 3 Ctrl, 5 NC, 6 +Vo, 7 0V, 8 CC

## ZY_WRBD-2W
designator U?
footprint ZY_WRBD-2W
pins: 1 GND, 7 NC, 8 NC, 9 +Vo, 10 0V, 16 Vin

## ZY_WRBD-3W
designator U?
footprint ZY_WRBD-3W (宽压输入隔离稳压单输出电源模块)
pins: 2 GND, 3 GND, 9 NC, 11 NC, 14 +Vo, 16 0V, 22 Vin, 23 Vin

## ZY_WRBD-5W
designator U?
footprint ZY_WRBD-5W
pins: 1 Vin, 2 GND, 3 0V, 5 +Vo

## ZY_WRBD-6W
designator U?
footprint ZY_WRBD-6W
pins: 2 GND, 3 GND, 11 NC, 14 +Vo, 16 0V, 22 Vin, 23 Vin

## ZY_WRBD-10W
designator U?
footprint ZY_WRBD-10W
pins: 1 Vin, 2 GND, 3 +Vo, 5 0V

## ZY_WRBDD-3W
designator U?
footprint ZY_WRBDD-3W
pins: 1 Vin, 2 GND, 3 +Vo, 5 0V

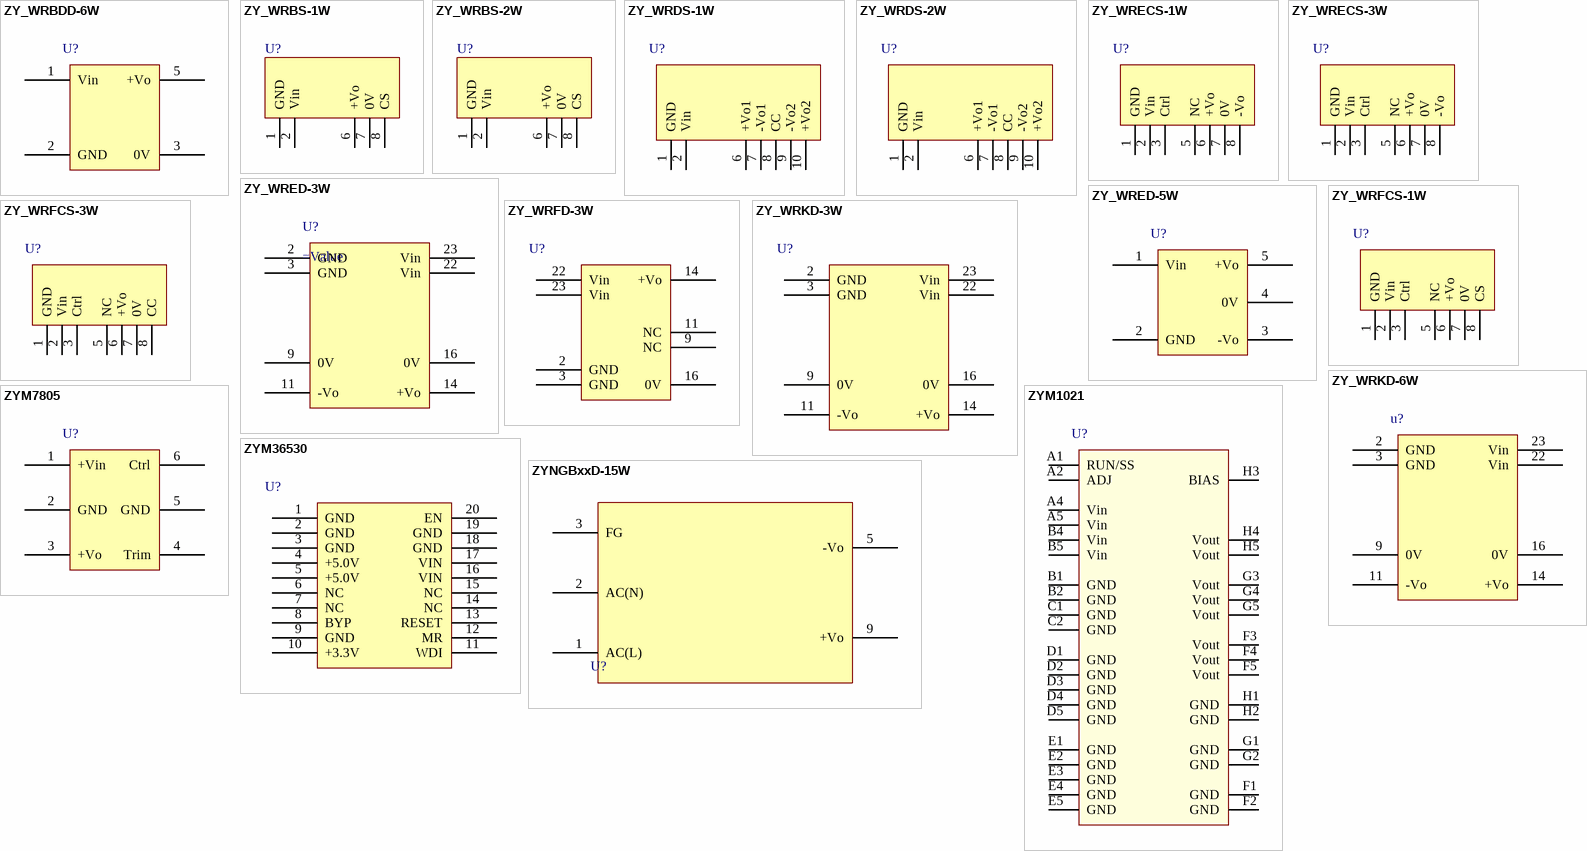
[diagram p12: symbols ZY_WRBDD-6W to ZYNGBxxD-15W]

## ZY_WRBDD-6W
designator U?
footprint ZY_WRBDD-6W
pins: 1 Vin, 2 GND, 3 0V, 5 +Vo

## ZY_WRBS-1W
designator U?
footprint ZY_WRBS-1W
pins: 1 GND, 2 Vin, 6 +Vo, 7 0V, 8 CS

## ZY_WRBS-2W
designator U?
footprint ZY_WRBS-2W
pins: 1 GND, 2 Vin, 6 +Vo, 7 0V, 8 CS

## ZY_WRDS-1W
designator U?
footprint ZY_WRDS-1W
pins: 1 GND, 2 Vin, 6 +Vo1, 7 -Vo1, 8 CC, 9 -Vo2, 10 +Vo2

## ZY_WRDS-2W
designator U?
footprint ZY_WRDS-2W
pins: 1 GND, 2 Vin, 6 +Vo1, 7 -Vo1, 8 CC, 9 -Vo2, 10 +Vo2

## ZY_WRECS-1W
designator U?
footprint ZY_WRECS-1W
pins: 1 GND, 2 Vin, 3 Ctrl, 5 NC, 6 +Vo, 7 0V, 8 -Vo

## ZY_WRECS-3W
designator U?
footprint ZY_WRECS-3W
pins: 1 GND, 2 Vin, 3 Ctrl, 5 NC, 6 +Vo, 7 0V, 8 -Vo

## ZY_WRED-3W
designator U?
footprint ZY_WRED-3W
pins: 2 GND, 3 GND, 9 0V, 11 -Vo, 14 +Vo, 16 0V, 22 Vin, 23 Vin

## ZY_WRED-5W
designator U?
footprint ZY_WRED-5W
pins: 1 Vin, 2 GND, 3 -Vo, 4 0V, 5 +Vo

## ZY_WRFCS-1W
designator U?
footprint ZY_WRFCS-1W
pins: 1 GND, 2 Vin, 3 Ctrl, 5 NC, 6 +Vo, 7 0V, 8 CS

## ZY_WRFCS-3W
designator U?
footprint ZY_WRFCS-3W
pins: 1 GND, 2 Vin, 3 Ctrl, 5 NC, 6 +Vo, 7 0V, 8 CC

## ZY_WRFD-3W
designator U?
footprint ZY_WRFD-3W
pins: 2 GND, 3 GND, 9 NC, 11 NC, 14 +Vo, 16 0V, 22 Vin, 23 Vin

## ZY_WRKD-3W
designator U?
footprint ZY_WRKD-3W
pins: 2 GND, 3 GND, 9 0V, 11 -Vo, 14 +Vo, 16 0V, 22 Vin, 23 Vin

## ZY_WRKD-6W
designator u?
footprint ZY_WRKD-6W
pins: 2 GND, 3 GND, 9 0V, 11 -Vo, 14 +Vo, 16 0V, 22 Vin, 23 Vin

## ZYM1021
designator U?
footprint ZYM1021
pins: A1 RUN/SS, A2 ADJ, A4 Vin, A5 Vin, B1 GND, B2 GND, B4 Vin, B5 Vin, C1 GND, C2 GND, D1 GND, D2 GND, D3 GND, D4 GND, D5 GND, E1 GND, E2 GND, E3 GND, E4 GND, E5 GND, F1 GND, F2 GND, F3 Vout, F4 Vout, F5 Vout, G1 GND, G2 GND, G3 Vout, G4 Vout, G5 Vout, H1 GND, H2 GND, H3 BIAS, H4 Vout, H5 Vout

## ZYM7805
designator U?
footprint ZYM7805
pins: 1 +Vin, 2 GND, 3 +Vo, 4 Trim, 5 GND, 6 Ctrl

## ZYM36530
designator U?
footprint ZYM36530
pins: 1 GND, 2 GND, 3 GND, 4 +5.0V, 5 +5.0V, 6 NC, 7 NC, 8 BYP, 9 GND, 10 +3.3V, 11 WDI, 12 MR, 13 RESET, 14 NC, 15 NC, 16 VIN, 17 VIN, 18 GND, 19 GND, 20 EN

## ZYNGBxxD-15W
designator U?
footprint ZYNGBxxD-15W (120426 修改 by kong)
pins: 1 AC(L), 2 AC(N), 3 FG, 5 -Vo, 9 +Vo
